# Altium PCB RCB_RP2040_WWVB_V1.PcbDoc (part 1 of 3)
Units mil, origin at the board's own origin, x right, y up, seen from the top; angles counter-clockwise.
Board outline 1250.1 x 2647.64 mil, 10 copper layers (L01-TOP, L02-GND, L03-SIG, L04-GND, L05-PWR, L06-PWR, L07-GND, L08-SIG, L09-GND, L10-BOT), stack 62.1 mil thick; 224 components, 123 nets, 635 pads, 542 vias.
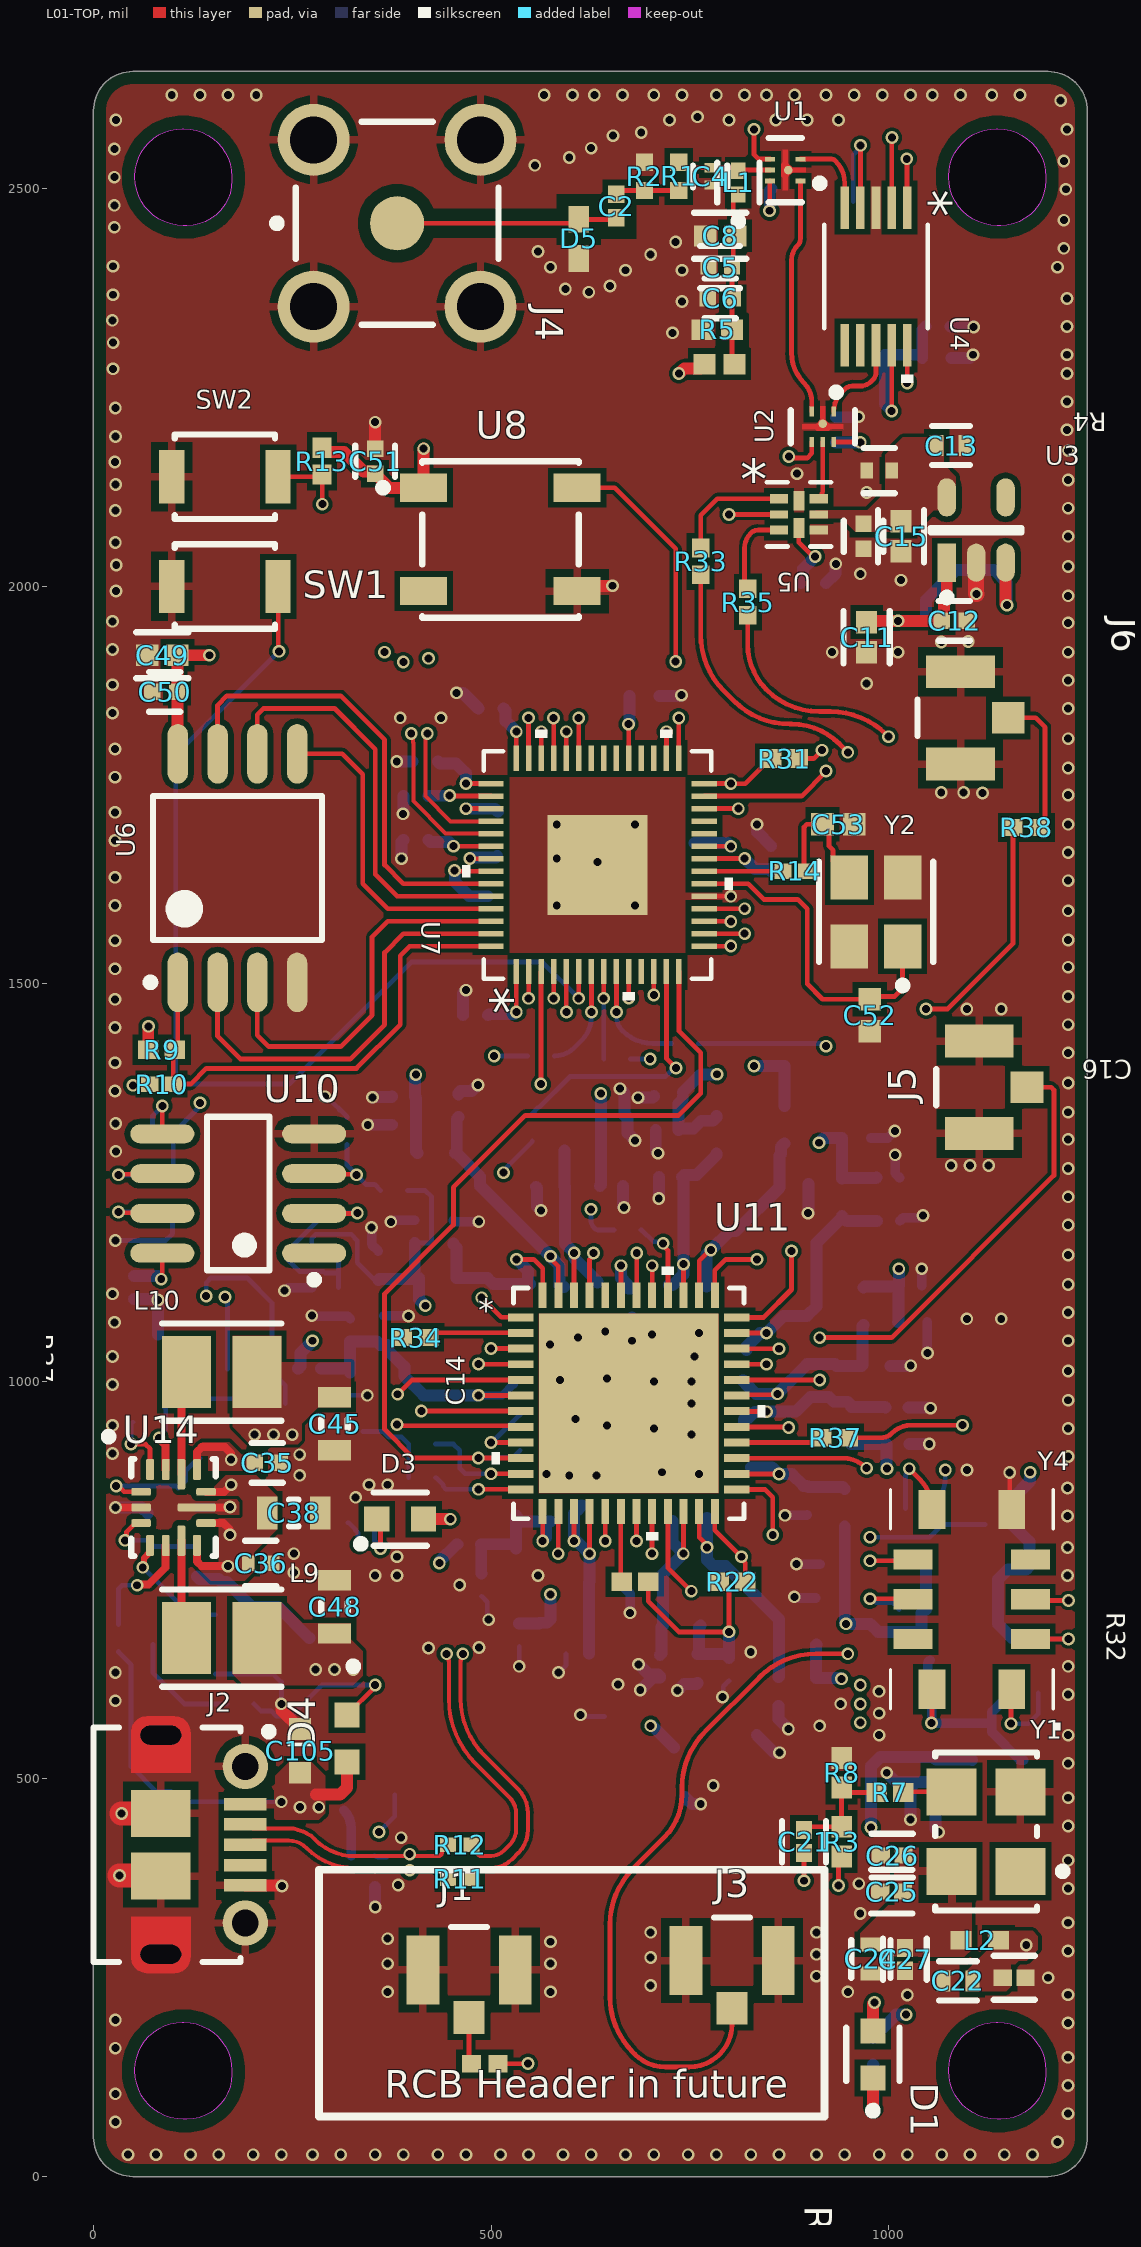
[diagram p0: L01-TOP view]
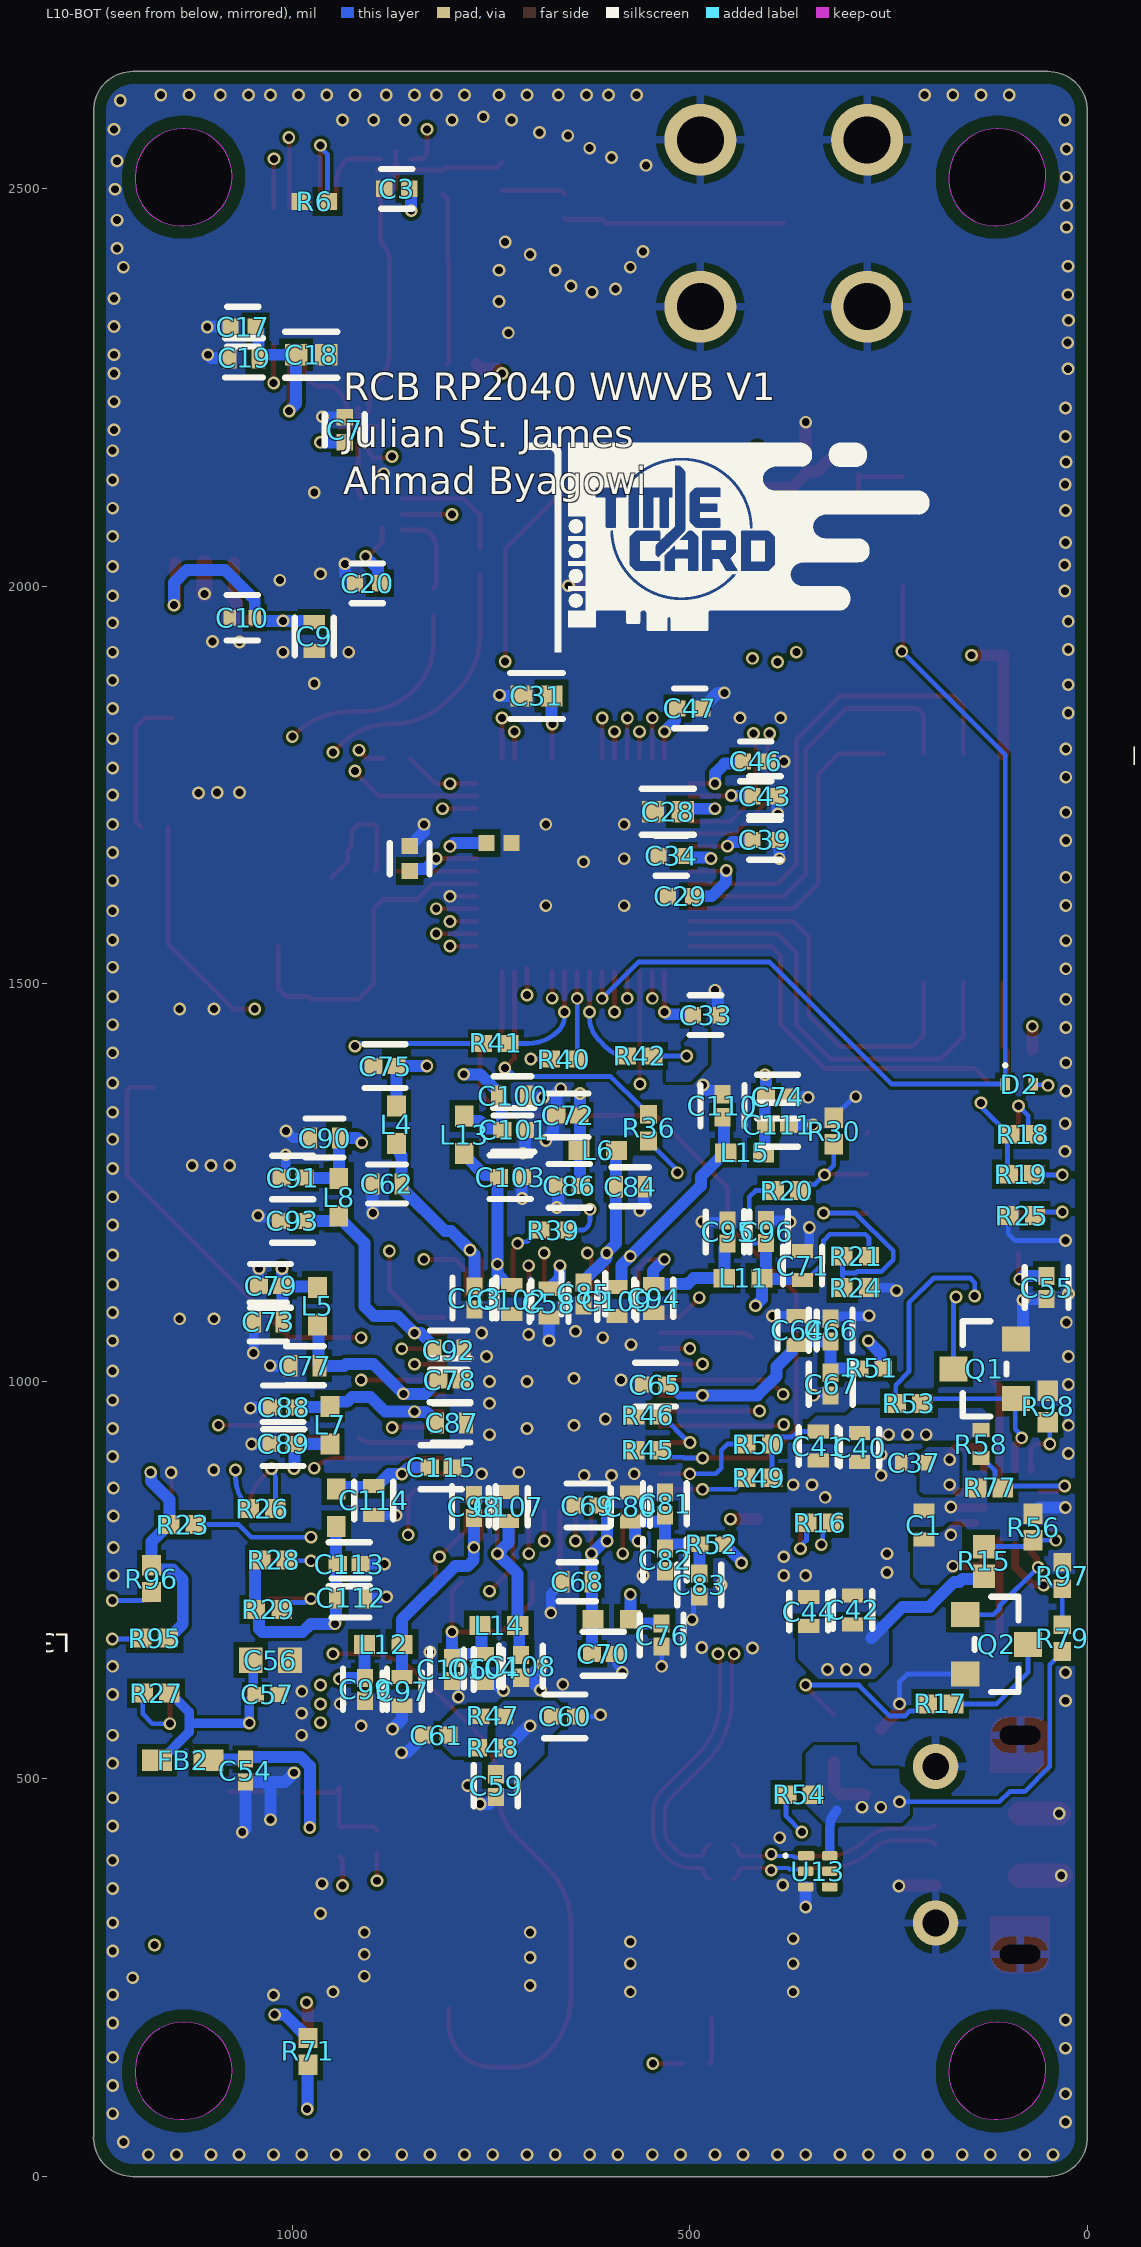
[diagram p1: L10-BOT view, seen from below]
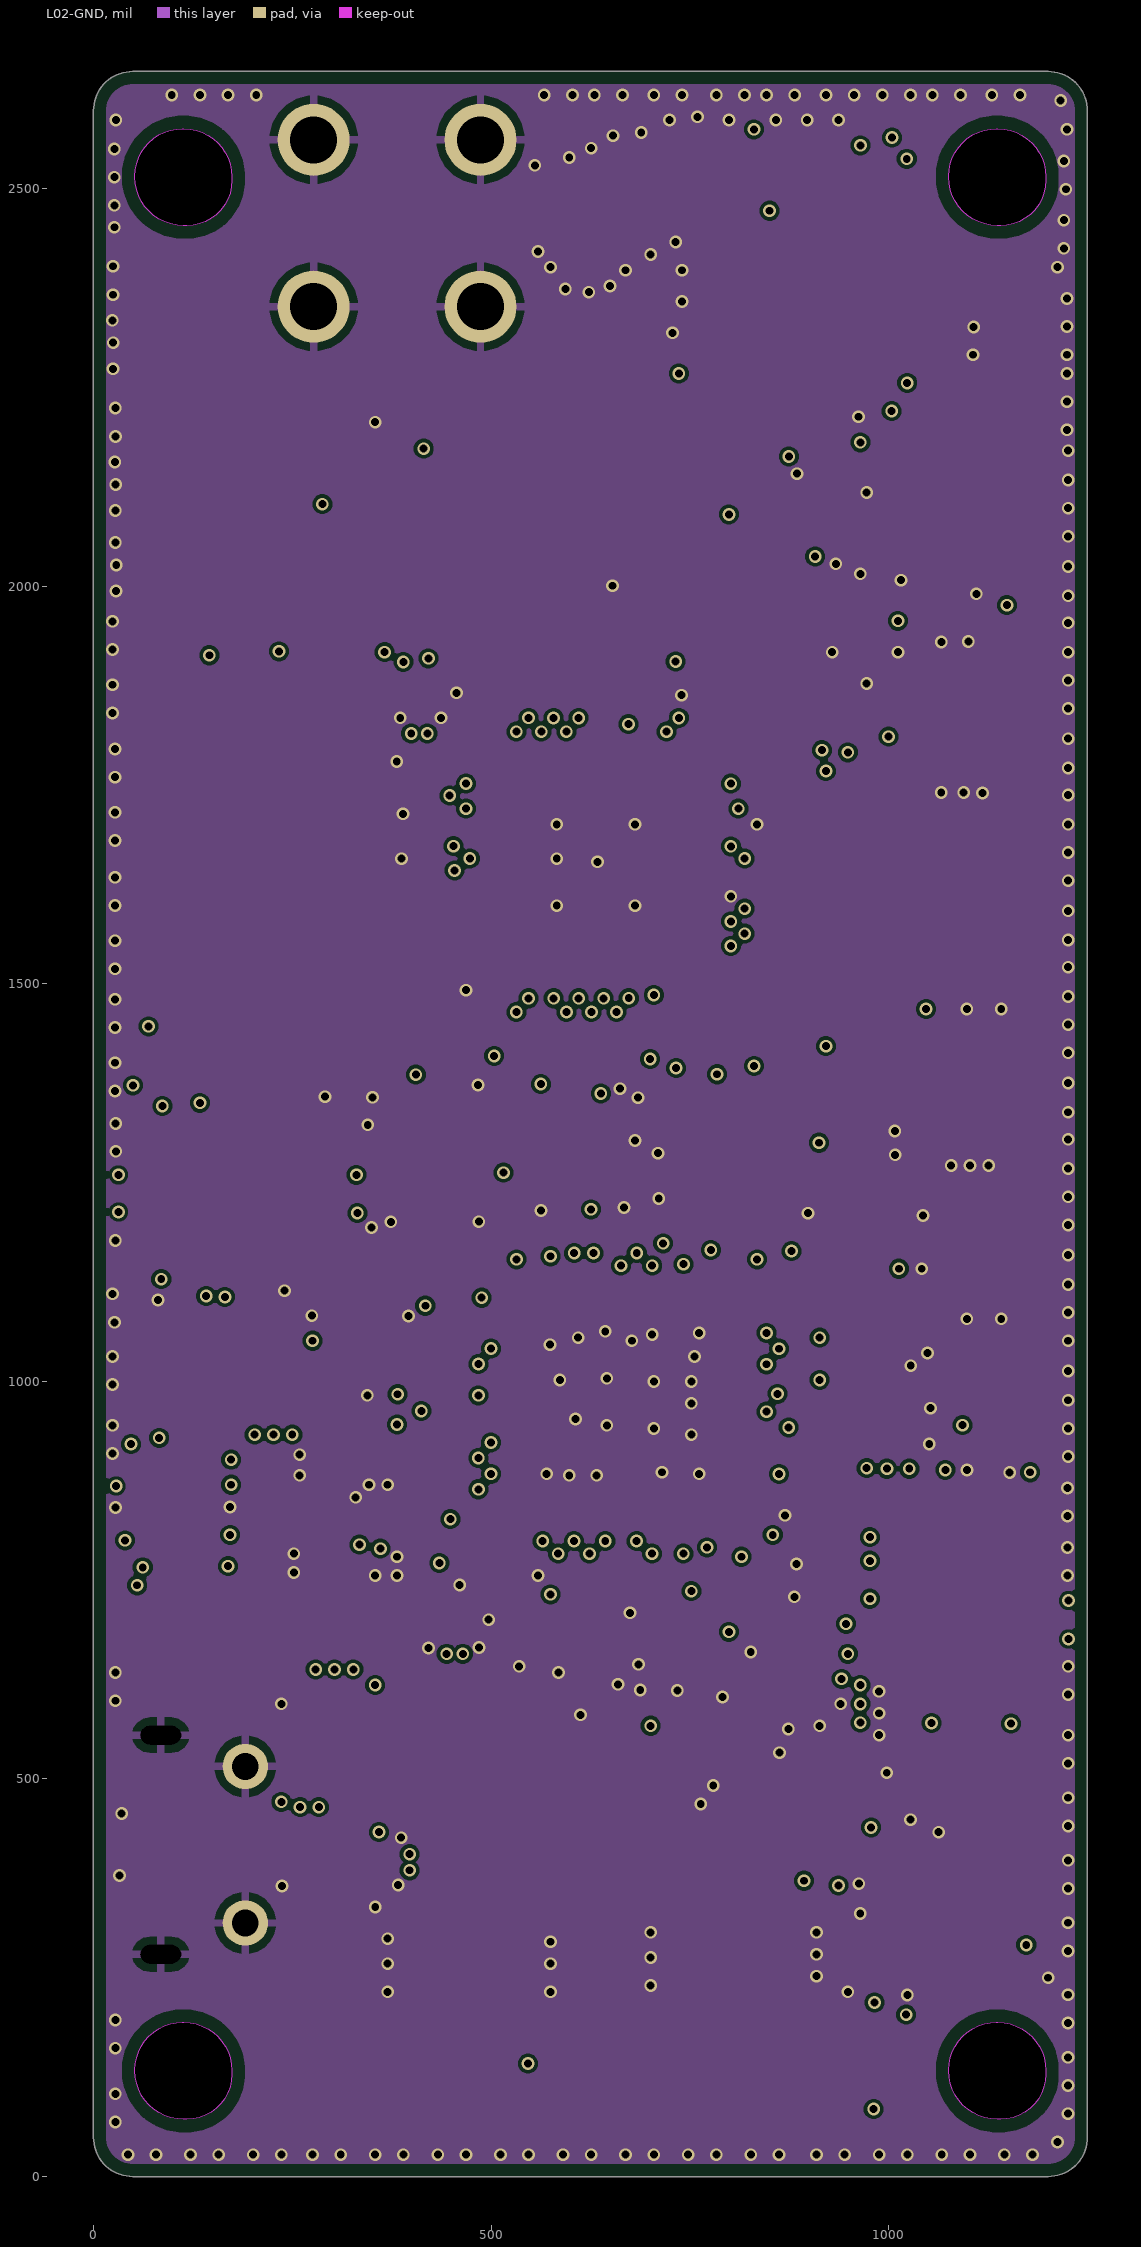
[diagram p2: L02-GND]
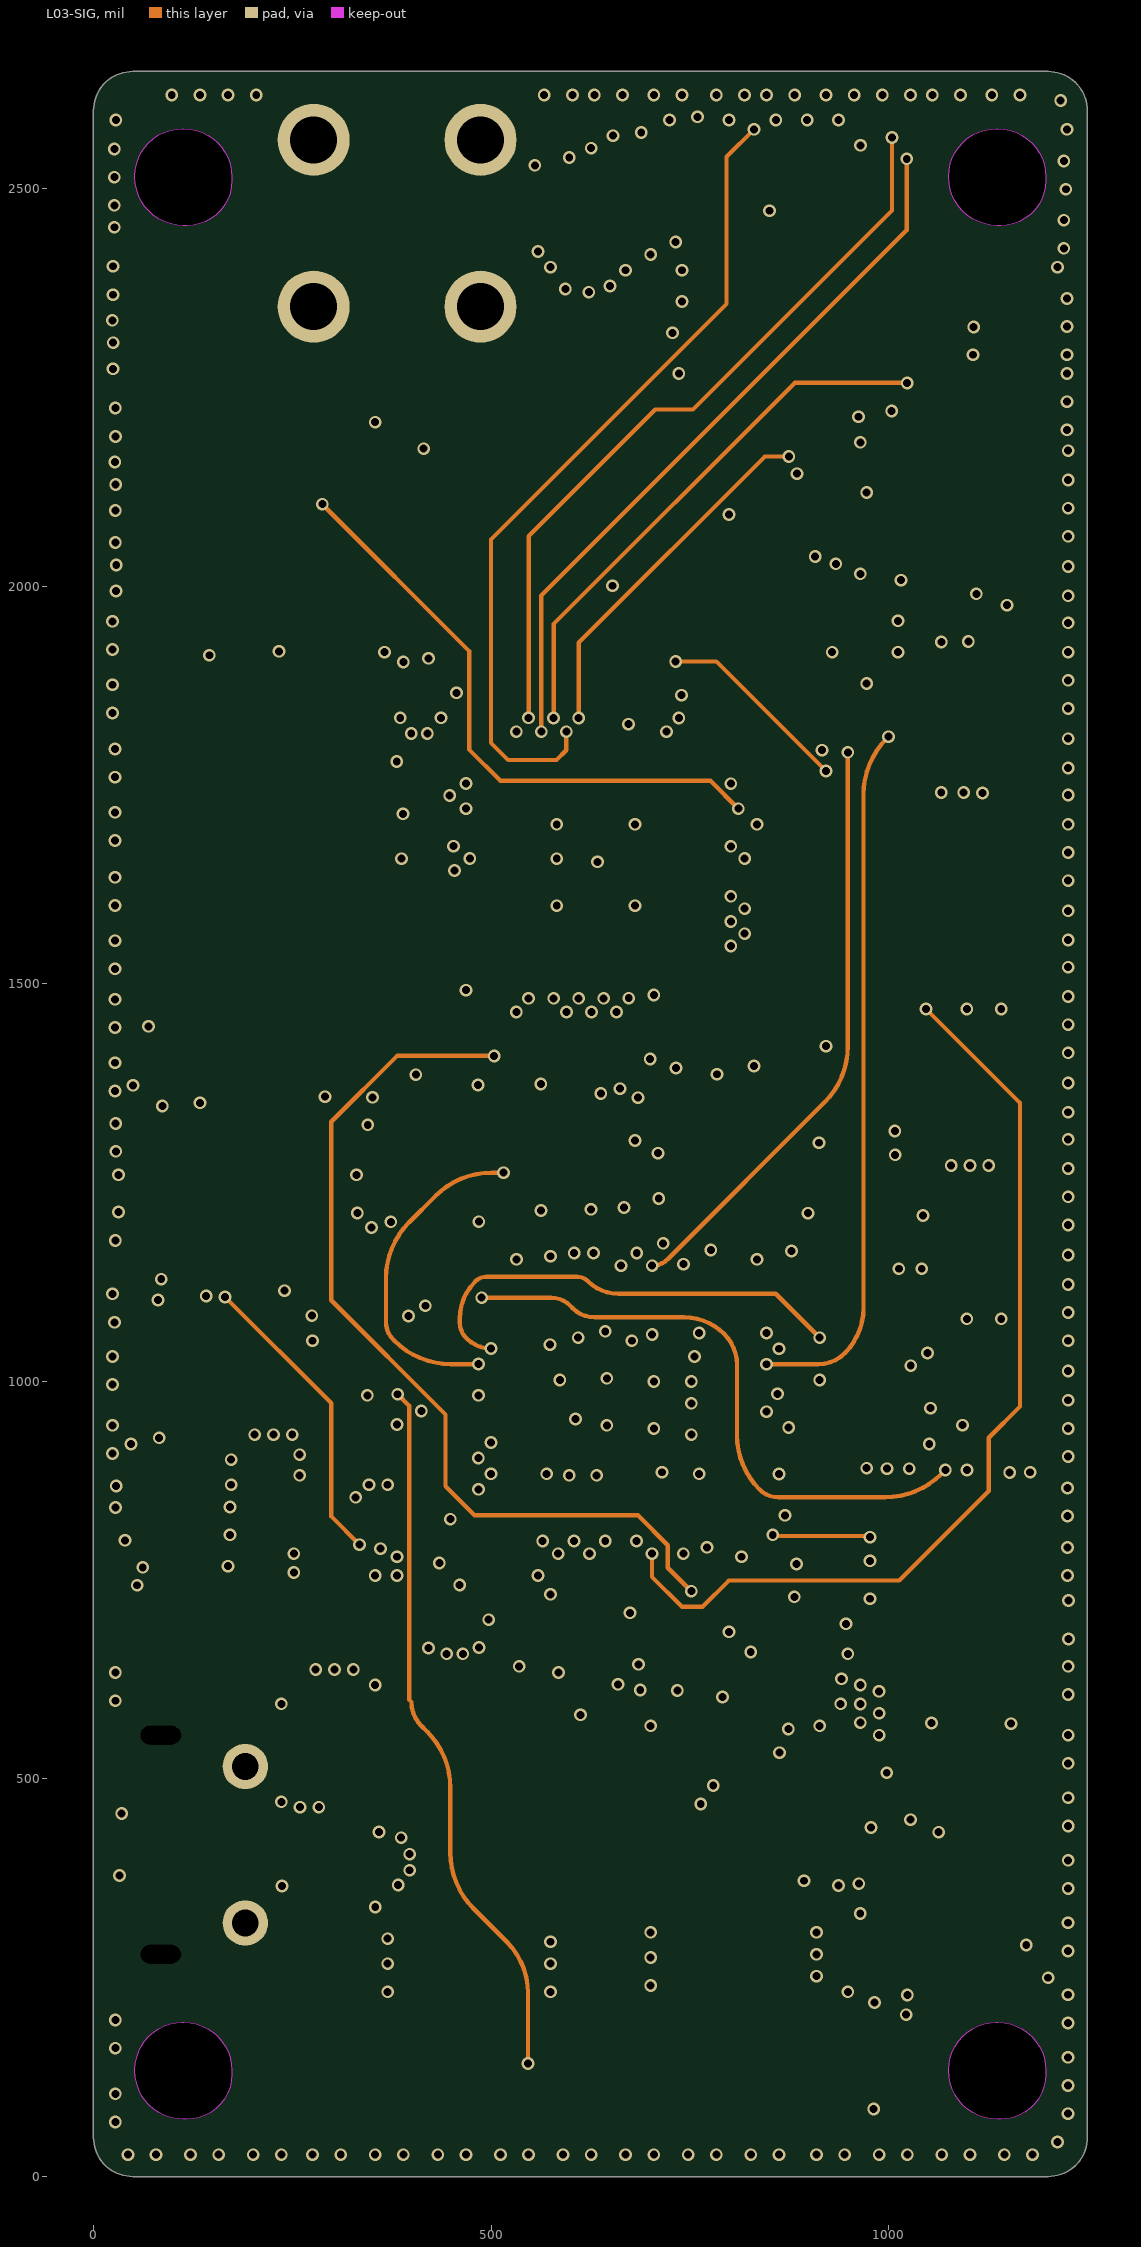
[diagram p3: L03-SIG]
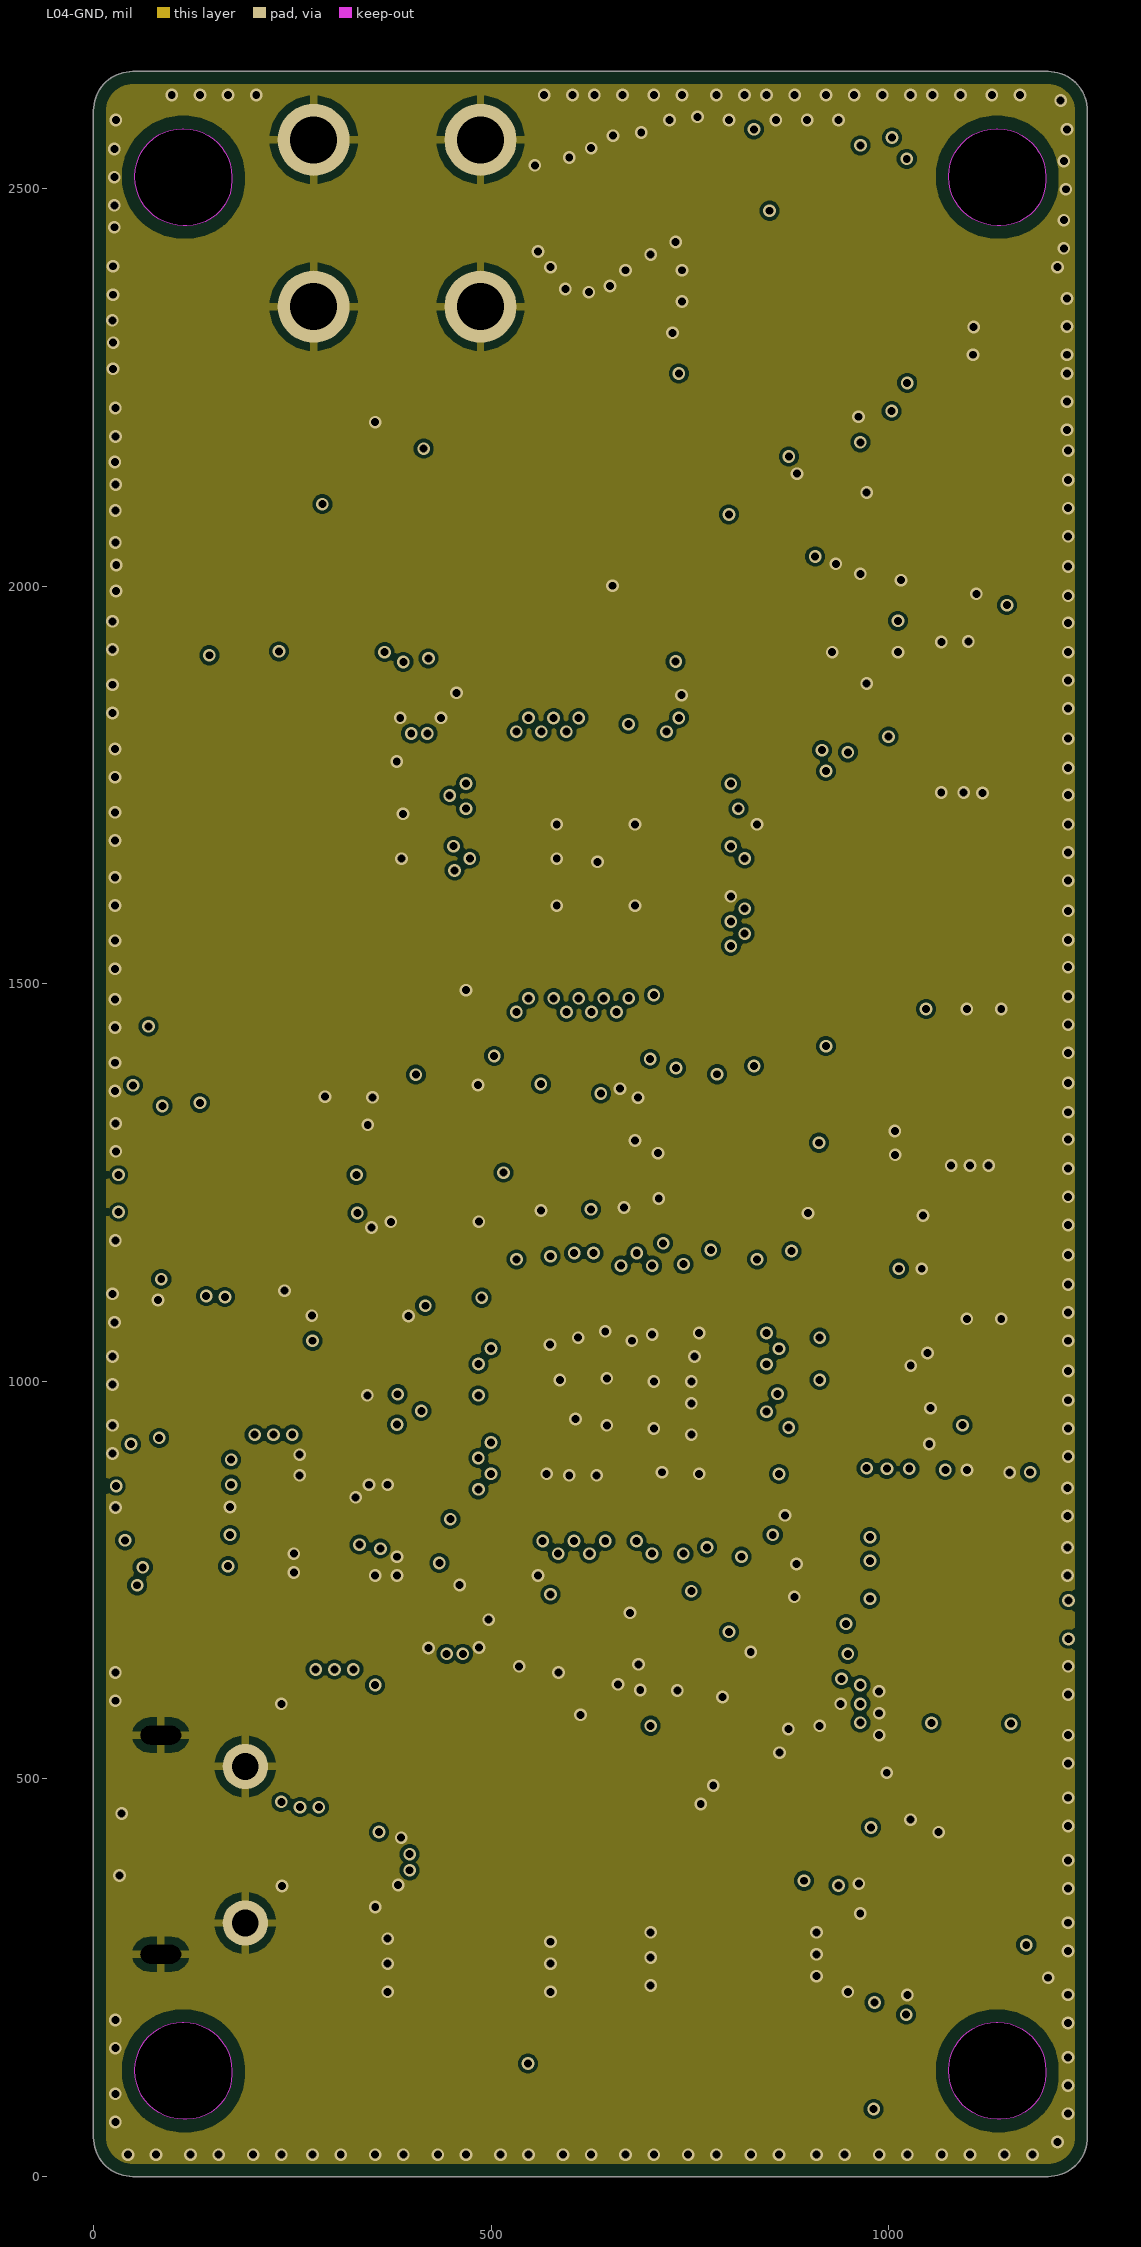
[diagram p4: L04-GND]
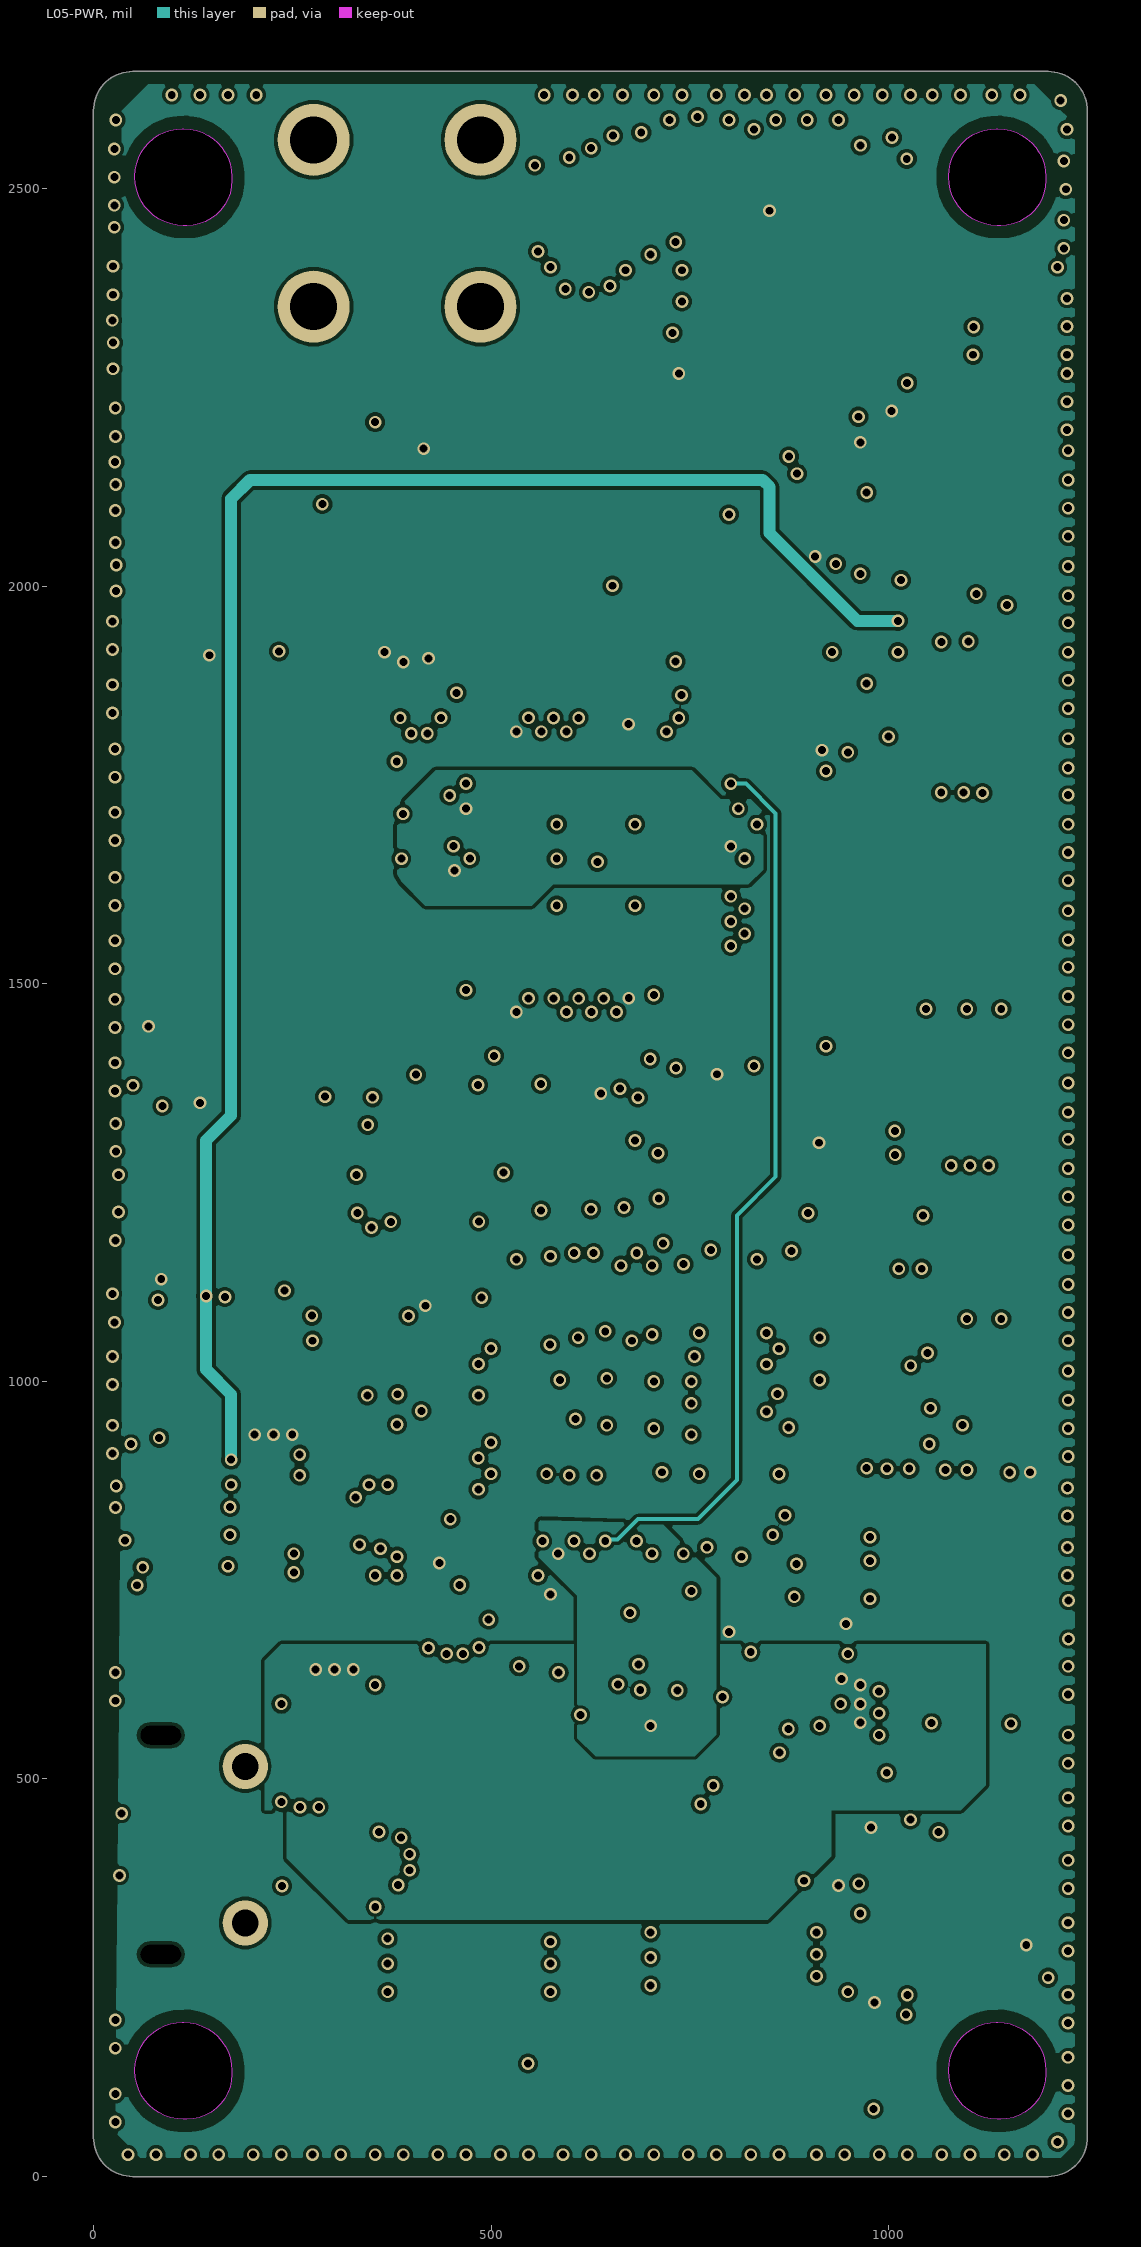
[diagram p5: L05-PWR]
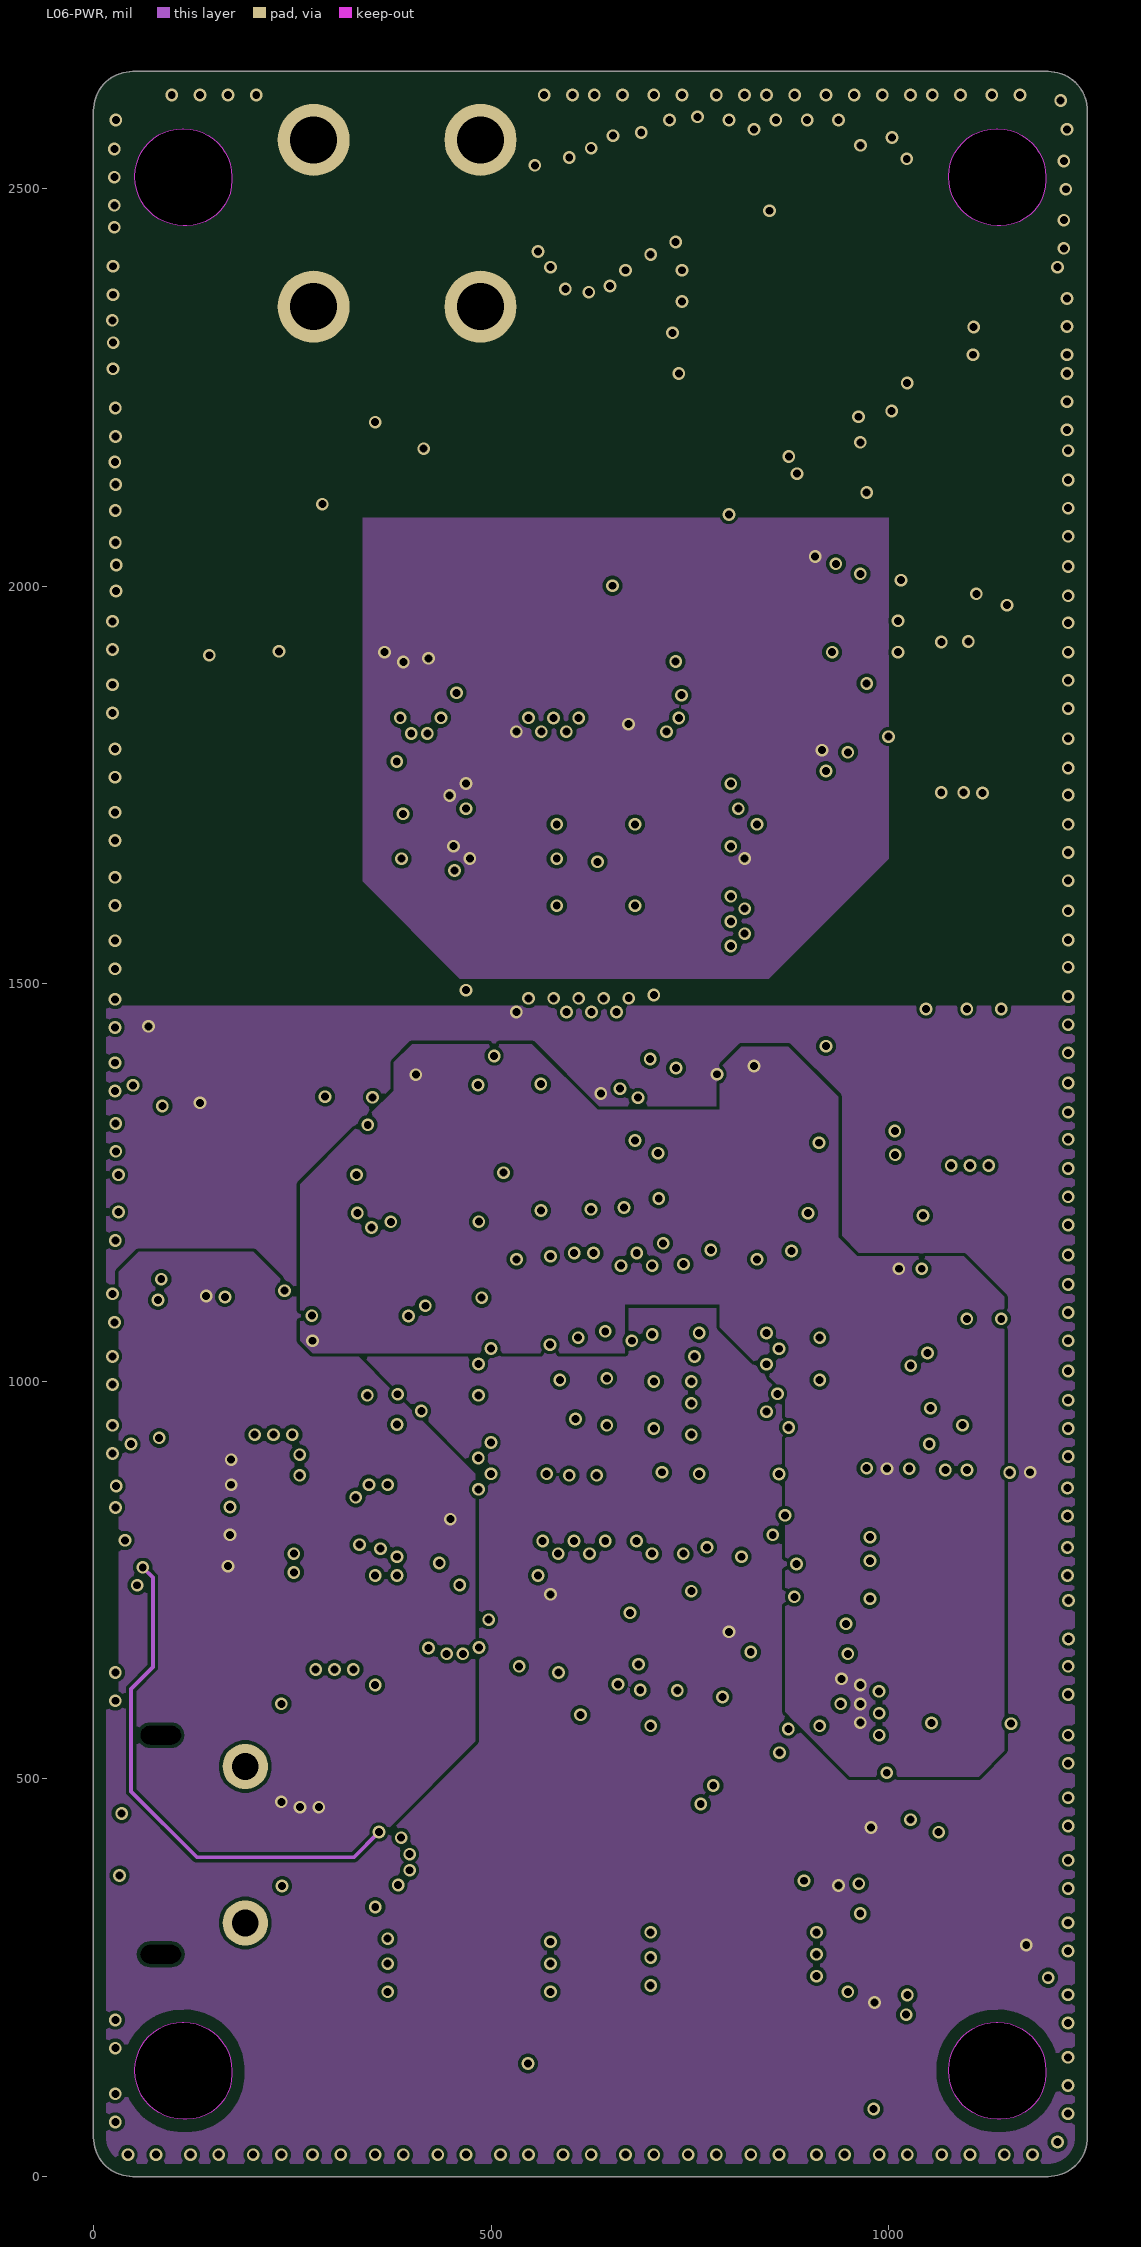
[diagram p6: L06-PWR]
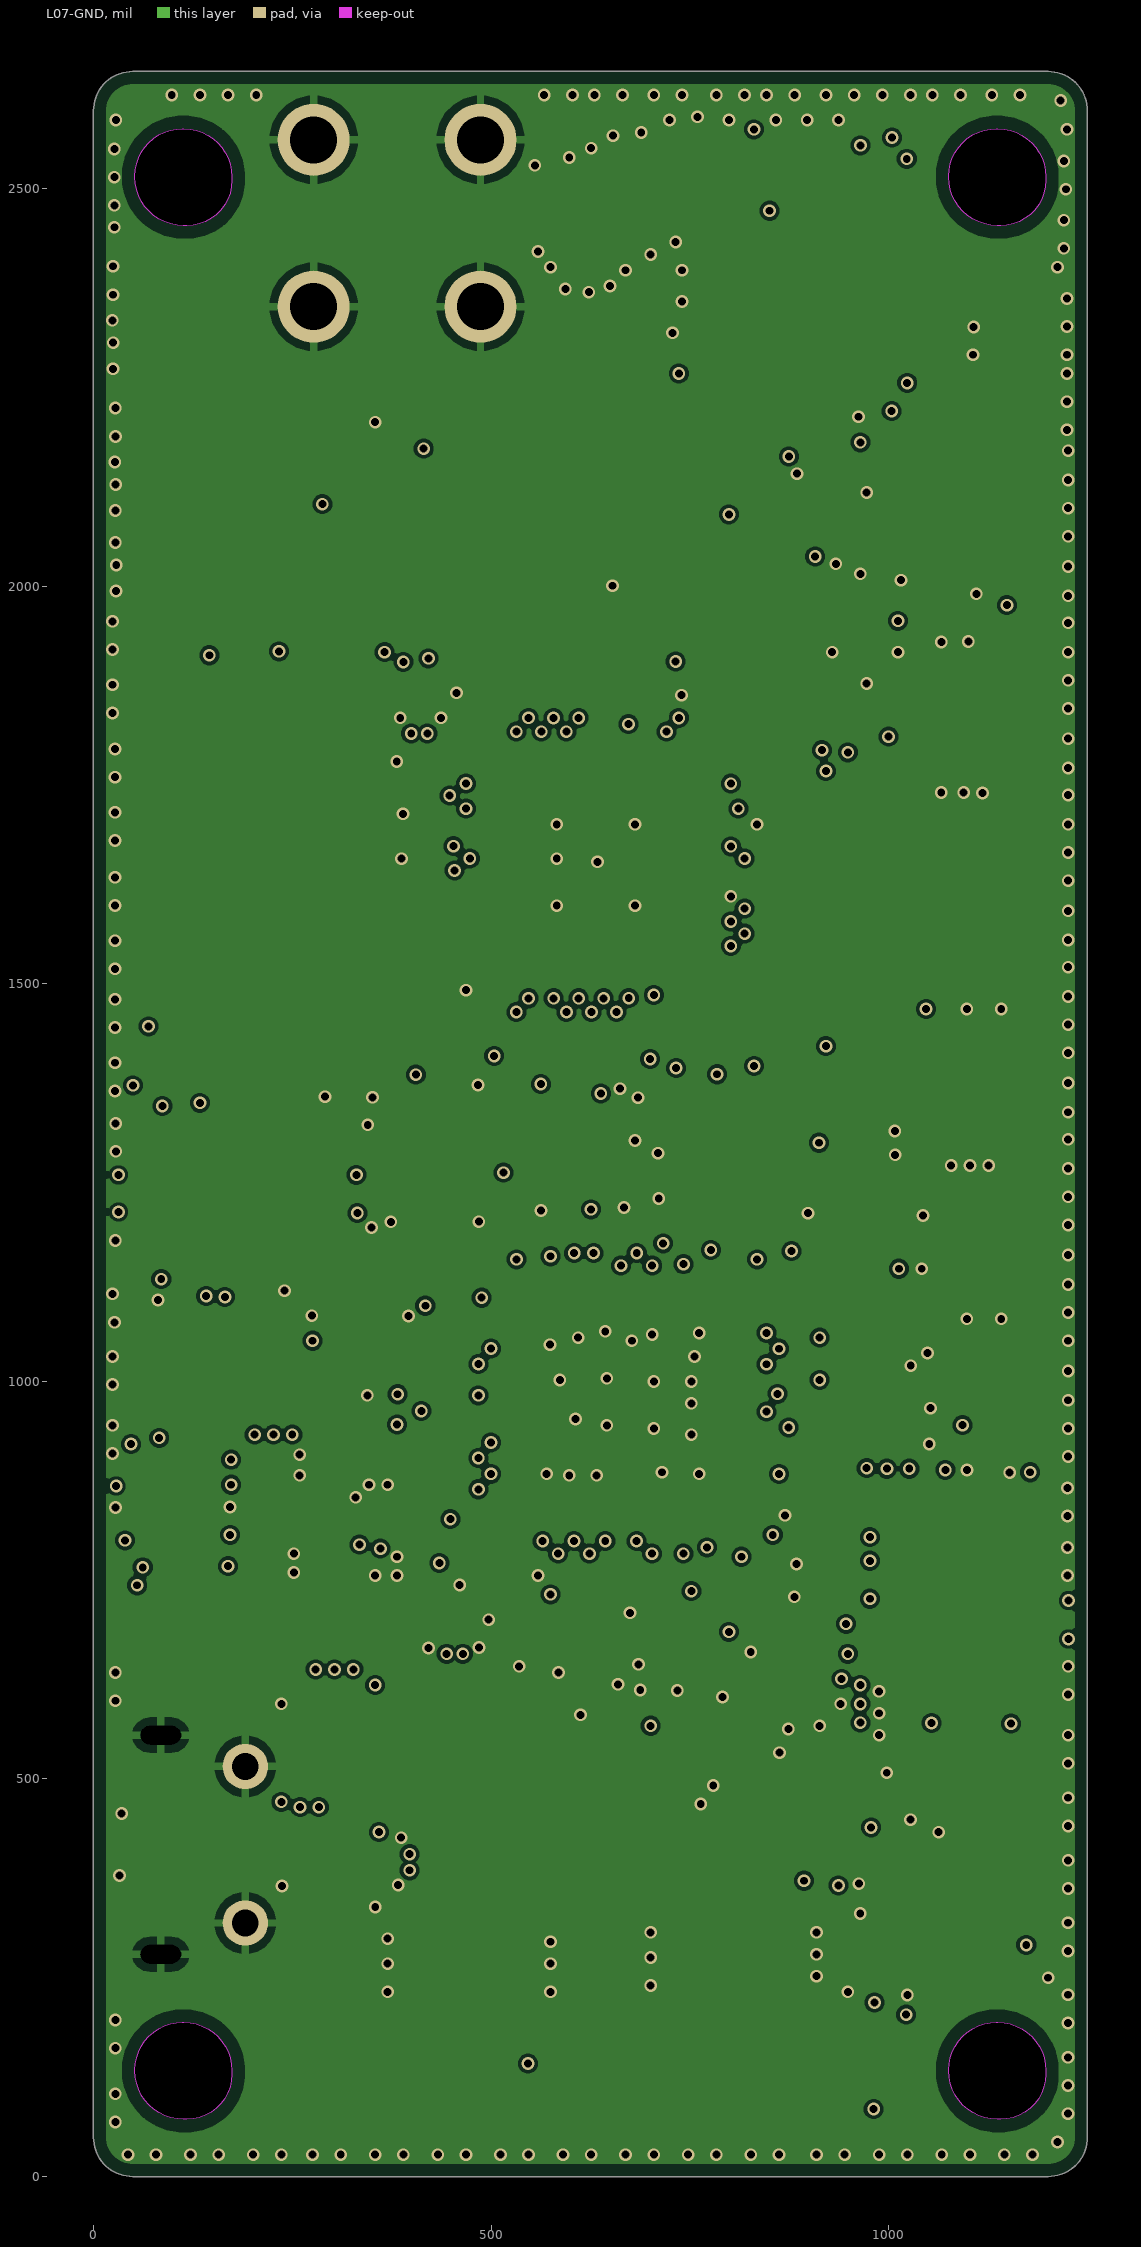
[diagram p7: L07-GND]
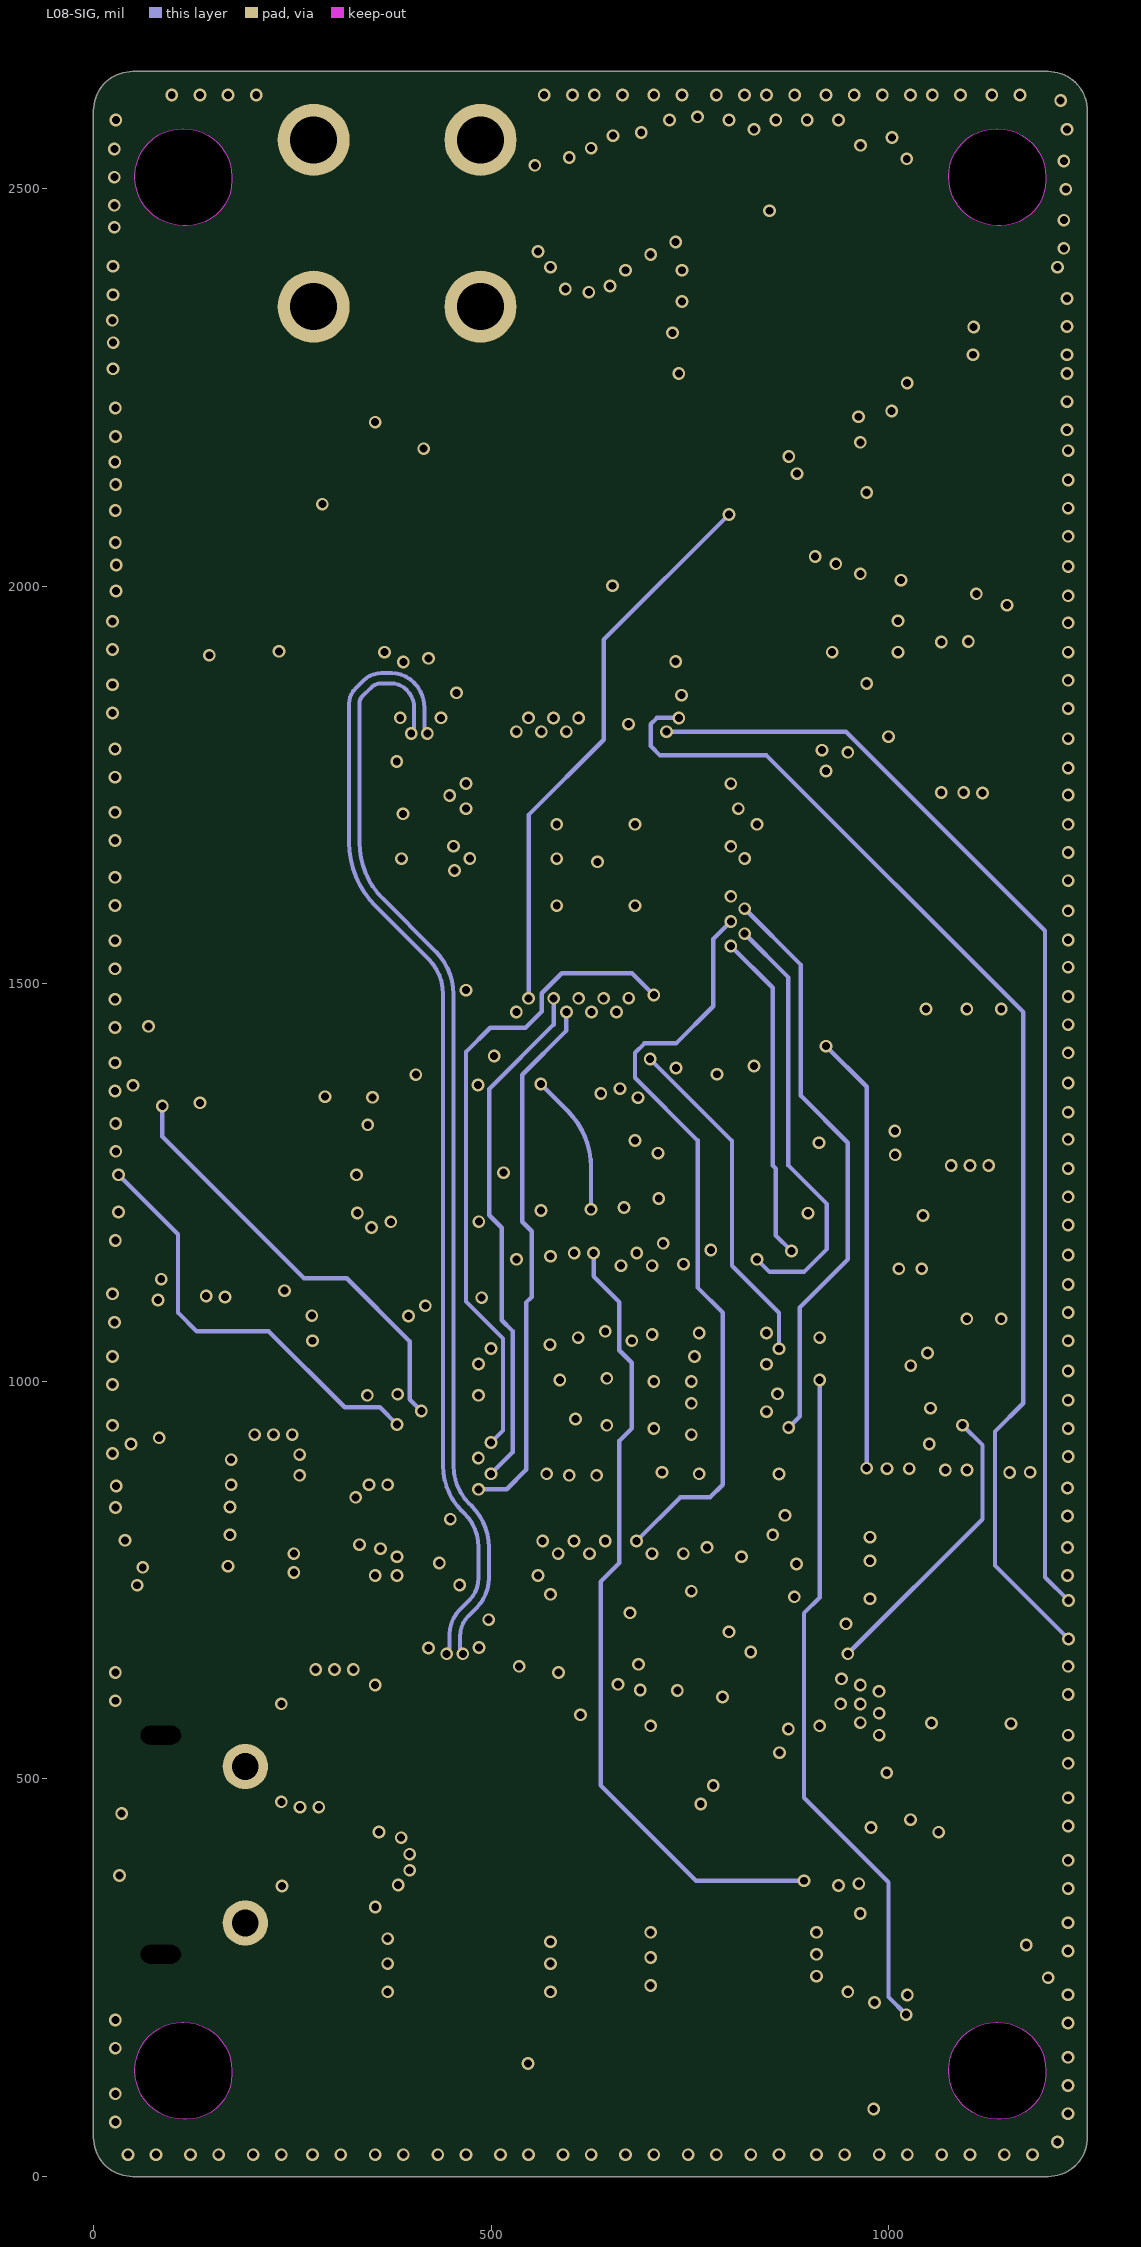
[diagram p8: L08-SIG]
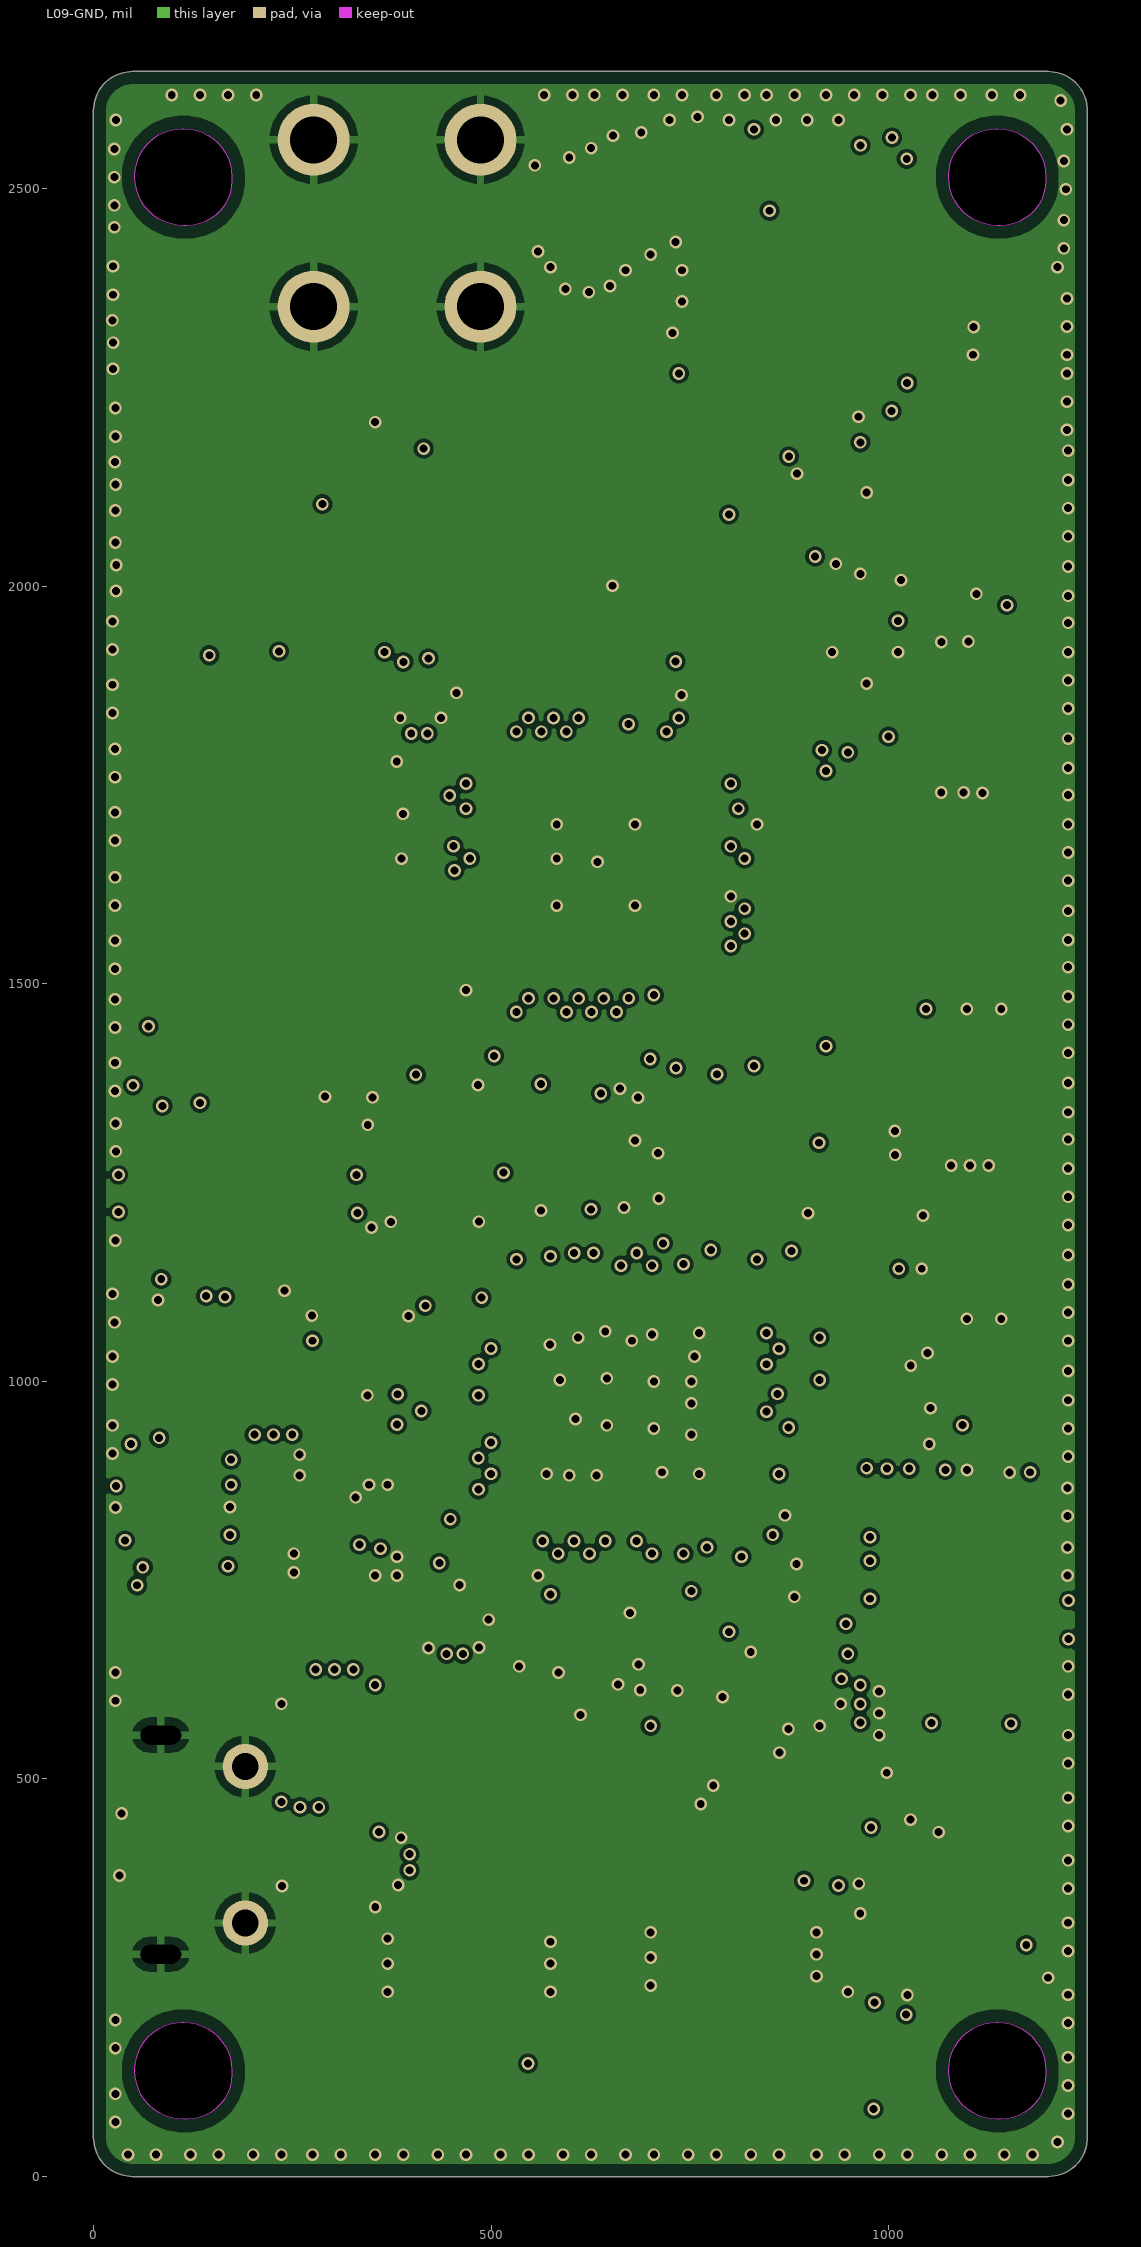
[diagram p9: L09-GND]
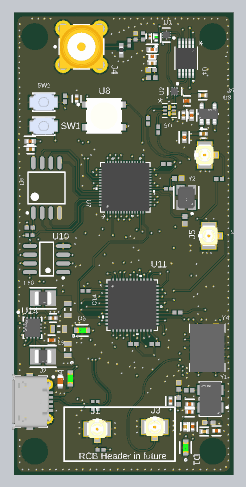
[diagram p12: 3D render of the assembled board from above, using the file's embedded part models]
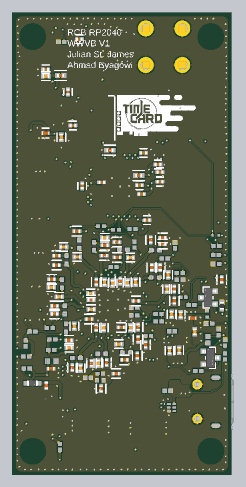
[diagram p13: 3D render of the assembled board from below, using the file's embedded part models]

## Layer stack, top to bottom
L01-TOP: signal copper 1.8
Dielectric 1: prepreg 3.9, 2116, Dk 4.29
L02-GND: signal copper 0.6
Dielectric 4: core 6, PP-006, Dk 4.29
L03-SIG: signal copper 0.6
Dielectric 6: prepreg 7.3, PP-006, Dk 4.29
L04-GND: signal copper 0.6
Dielectric 8: core 6, PP-006, Dk 4.29
L05-PWR: signal copper 0.6
Dielectric 5: prepreg 7.3, PP-006, Dk 4.29
L06-PWR: signal copper 0.6
Dielectric 9: core 6, PP-006, Dk 4.29
L07-GND: signal copper 0.6
Dielectric 7: prepreg 7.3, PP-006, Dk 4.29
L08-SIG: signal copper 0.6
Dielectric 2: core 6, PP-006, Dk 4.29
L09-GND: signal copper 0.6
Dielectric 3: prepreg 3.9, 2116, Dk 4.29
L10-BOT: signal copper 1.8

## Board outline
49.31,0 cw(c49.31,49.31) 0,49.31 0,2598.33 cw(c49.31,2598.33) 49.31,2647.64 1200.79,2647.64 1200.69,2647.64 cw(c1200.69,2598.33) 1250,2598.33 1250,49.31 1250.1,49.31 cw(c1200.79,49.31) 1200.79,0
cut-out: 1137.37,193.9 cw(c1137.37,133.57) 1197.69,133.57 1197.69,128.69 cw(c1140.85,128.69) 1140.85,71.85 1136.75,71.85 cw(c1136.75,132.81) 1075.79,132.81 1075.79,134.11 cw(c1135.57,134.11) 1135.57,193.89
cut-out: 113.75,2575.79 cw(c113.75,2515.46) 174.07,2515.46 174.07,2510.58 cw(c117.23,2510.58) 117.23,2453.74 113.13,2453.74 cw(c113.13,2514.7) 52.17,2514.7 52.17,2516 cw(c111.95,2516) 111.95,2575.78
cut-out: 1137.37,2575.79 cw(c1137.37,2515.46) 1197.69,2515.46 1197.69,2510.58 cw(c1140.85,2510.58) 1140.85,2453.74 1136.75,2453.74 cw(c1136.75,2514.7) 1075.79,2514.7 1075.79,2516 cw(c1135.57,2516) 1135.57,2575.78
cut-out: 113.75,193.9 cw(c113.75,133.57) 174.07,133.57 174.07,128.69 cw(c117.23,128.69) 117.23,71.85 113.13,71.85 cw(c113.13,132.81) 52.17,132.81 52.17,134.11 cw(c111.95,134.11) 111.95,193.89

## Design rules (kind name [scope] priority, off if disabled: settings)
AcuteAngle [All] p1: minimum=6.00000000000000E+0001 checktracksonly=FALSE
BoardOutlineClearance [All] p1: gap=15.75 ignorepadtopadclearanceinfootprint=FALSE
Clearance Clearance_RF [InNetClass('RF')] p1: gap=15 ignorepadtopadclearanceinfootprint=FALSE except(4.3: SMDPad-SMDPad SMDPad-THPad SMDPad-Via SMDPad-Text SMDPad-Hole THPad-THPad THPad-Via THPad-Text THPad-Hole Via-Via Via-Fill Via-Poly Via-Region Via-Text Via-Hole Text-Text Text-Hole)
Clearance [All] p2: gap=4.3 ignorepadtopadclearanceinfootprint=FALSE except(7: SMDPad-Fill SMDPad-Poly SMDPad-Region)
ComponentClearance [All] p1: gap=15.75 collisioncheckmode=3 verticalgap=19.68 showdistances=FALSE
DiffPairsRouting 100_Ohm_Default [InDifferentialPairClass('All Differential Pairs')] p1: maxlimit=10 minlimit=4.43 mostfreqgap=6.68 toplayer_mingap=10 toplayer_prefgap=10 toplayer_minwidth=5 toplayer_maxwidth=5 toplayer_prefwidth=5 midlayer3_mingap=8 midlayer3_maxgap=8 midlayer3_prefgap=8 midlayer3_minwidth=5 midlayer3_maxwidth=5 midlayer3_prefwidth=5 midlayer4_mingap=8 midlayer4_maxgap=8 midlayer4_prefgap=8 midlayer4_minwidth=5 midlayer4_maxwidth=5 midlayer4_prefwidth=5 bottomlayer_mingap=10 bottomlayer_prefgap=10 bottomlayer_minwidth=5 bottomlayer_maxwidth=5 bottomlayer_prefwidth=5 impedanceprofiledriven=TRUE impedanceprofileid={6D9B781E-2234-44CB-9805-C73247B854E7} impedanceprofilevalue=100.000000 maxuncoupledlength=200
HoleSize [All] p1: absolutevalues=TRUE maxlimit=118.11 minlimit=5.91 maxpercent=80.000 minpercent=20.000
HoleToHoleClearance [All] p1: gap=11.81 allowstackedmicrovias=TRUE
MatchedLengths [InDifferentialPairClass('All Differential Pairs')] p1: tolerance=10 checknetsindiffpair=TRUE checkdiffpairvsdiffpair=FALSE checkxsignals=FALSE checkothers=FALSE
MinimumSolderMaskSliver [All] p1: minsoldermaskwidth=3.94 // 0.076mm for Green Soldermask, 0.1 for other color soldermask
PlaneClearance [All] p1: clearance=10
PolygonConnect TH_PolyConnect [HasFootprint('FP-SMA-J-P-H-ST-MT1-MFG') OR HasFootprint('FP-HTSW-104-07-G-D-MFG') OR HasFootprint('USB-MICRO-B_V') OR HasFootprint('FP-U_FL-R-SMT-1_10-MFG') OR HasFootprint('ADA-RGB-1655_V') OR HasFootprint('FP-B3U-1000P-MFG') OR HasFootprint('MCHP-SOIC-SN8_N') OR HasFootprint('FP-SiT5001-3-MFG')] p1: connectstyle=Relief reliefconductorwidth=10 reliefentries=4 polygonreliefangle="90 Angle" airgapwidth=10
PolygonConnect [All] p2: connectstyle=Direct reliefconductorwidth=20 reliefentries=4 polygonreliefangle="90 Angle" airgapwidth=10
RoutingCorners [All] p1: cornerstyle=45-Degree minsetback=98.43 maxsetback=98.43
RoutingVias [All] p1: holewidth=10 width=16 viastyle="Through Hole" minholewidth=10 minwidth=16 maxholewidth=11.81 maxwidth=23.62
SilkToSilkClearance [All] p1: silktosilkclearance=3.94
SilkToSolderMaskClearance [IsPad] p1: minsilkscreentomaskgap=5 clearancetoexposedcopper=TRUE
SolderMaskExpansion [All] p1: expansion=1.97 istentingtop=FALSE
SupplyNets "Schematic Supply Nets_24" [InNet('TX_VFBSD')] p1: voltage=0.000
SupplyNets "Schematic Supply Nets_23" [InNet('RX_VFBSD')] p2: voltage=0.000
SupplyNets "Schematic Supply Nets_22" [InNet('RX_VDD')] p3: voltage=0.000
SupplyNets "Schematic Supply Nets_21" [InNet('TX_VDD')] p4: voltage=0.000
SupplyNets "Schematic Supply Nets_20" [InNet('DPLL_VDD_GPIO')] p5: voltage=0.000
SupplyNets "Schematic Supply Nets_19" [InNet('DPLL_VDDA_FB')] p6: voltage=0.000
SupplyNets "Schematic Supply Nets_18" [InNet('DPLL_VDDO_Q9')] p7: voltage=0.000
SupplyNets "Schematic Supply Nets_17" [InNet('DPLL_VDDA_BG_LC')] p8: voltage=0.000
SupplyNets "Schematic Supply Nets_16" [InNet('DPLL_VDDA_PDCP_XTAL')] p9: voltage=0.000
SupplyNets "Schematic Supply Nets_15" [InNet('P1V8')] p10: voltage=0.000
SupplyNets "Schematic Supply Nets_14" [InNet('DPLL_VDD_DCO_Q11')] p11: voltage=0.000
SupplyNets "Schematic Supply Nets_13" [InNet('P3V3')] p12: voltage=0.000
SupplyNets "Schematic Supply Nets_12" [InNet('GND')] p13: voltage=0.000
SupplyNets "Schematic Supply Nets_11" [InNet('DPLL_VDD_DCO_Q9')] p14: voltage=0.000
SupplyNets "Schematic Supply Nets_10" [InNet('DPLL_VDD_DCO_Q10')] p15: voltage=0.000
SupplyNets "Schematic Supply Nets_9" [InNet('DPLL_VDDO_Q10')] p16: voltage=0.000
SupplyNets "Schematic Supply Nets_8" [InNet('DPLL_VDD_DIG')] p17: voltage=0.000
SupplyNets "Schematic Supply Nets_7" [InNet('VIN')] p18: voltage=0.000
SupplyNets "Schematic Supply Nets_6" [InNet('DPLL_VDD_DCO_Q8')] p19: voltage=0.000
SupplyNets "Schematic Supply Nets_5" [InNet('DPLL_VDDO_Q8')] p20: voltage=0.000
SupplyNets "Schematic Supply Nets_4" [InNet('DPLL_VDD_CLK')] p21: voltage=0.000
SupplyNets "Schematic Supply Nets_3" [InNet('DPLL_VDDO_Q11')] p22: voltage=0.000
SupplyNets "Schematic Supply Nets_2" [InNet('RP_CORE')] p23: voltage=0.000
SupplyNets "Schematic Supply Nets_1" [InNet('ADC_AVDD')] p24: voltage=0.000
SupplyNets "Schematic Supply Nets" [InNet('VBUS_USB')] p25: voltage=0.000
UnRoutedNet [All] p1: checkbadconnections=TRUE
Width [All] p1: maxlimit=100 minlimit=4 preferedwidth=5 toplayer_maxwidth=40 toplayer_prefwidth=6 midlayer3_maxwidth=40 midlayer3_prefwidth=5.5 midlayer4_maxwidth=40 midlayer4_prefwidth=5.5 bottomlayer_maxwidth=40 bottomlayer_prefwidth=6 impedanceprofiledriven=TRUE impedanceprofileid={F524FB06-5728-4647-A49A-4CD393059D1D} impedanceprofilevalue=50.000000 minimp=50.000000 maximp=50.000000 favimp=50.000000
20 further rules are at their usual default settings.

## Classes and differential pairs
component class 07-STM32WL3-TX: U7 U8
component class 06-STM32WL3-RX: D2 SW1 SW2 U5 U6
component class 11-Ice40_FPGA: C7 C74 C104 C106 C107 D4 R15 R16 R17
component class 06-Si5341_PLL: L16 Y1
component class 08-Power: C1 C35 C36 C37 C38 C40 C41 C42 C44 C45 C48 D3 D4 L9 L10 Q1 Q2 R15 R16 R17 R53 R54 R56 R58 R77 R79 R97 R98 U14
component class 07-USB-Prog: C105 J2 U13
component class 04-8A34004_DPLL-2: C62 C63 C64 C65 C66 C67 C68 C69 C70 C71 C72 C73 C74 C75 C76 C77 C78 C79 C80 C81 C82 C83 C84 C85 C86 C87 C88 C89 C90 C91 C92 C93 C94 C95 C96 C97 C98 C99 C100 C101 C102 C103 C104 C106 C107 C108 C109 C110 C111 C112 C113 C114 C115 L3 L4 L5 L6 L7 L8 L11 L12 L13 L14 L15 L16 R51 R52
component class 03-8A34004_DPLL-1: C55 C58 C59 C60 C61 D1 J1 J3 J5 J6 R18 R19 R20 R21 R22 R23 R24 R25 R30 R31 R32 R33 R34 R35 R36 R37 R38 R39 R40 R41 R42 R44 R45 R46 R47 R48 R49 R50 R71 U10 U11
component class 05-TCXO_Crystal: C21 C22 C23 C24 C25 C26 C27 C54 C56 C57 FB2 L2 R3 R7 R8 R26 R27 R28 R29 R95 R96 Y1 Y4
component class 05-SX1276: C31 C32 C33 C34 C39 C43 C46 C47 C49 C58 C59 C60 C101 C102 C103 C108 C109 C110 C111 C112 C113 C114 C115 L7 L8 L11 L12 L13 L14 L15 R23 R32 R33 R46 R47 R48 R49 R50 R51 R52
component class 04-SX1257: C9 C11 C12 C13 C14 C15 C16 C17 C18 C19 C20 C21 C22 C23 C24 C25 C26 C27 C28 C29 L1 L2 L3 R7 R14 U4 U5
component class 02-WWVB_Path: C2 C3 C4 C5 C6 C7 C8 C9 C10 C11 C12 C13 C14 C15 C16 C17 C18 C19 C20 L1 R1 R2 R4 R5 R6 U1 U2 U3 U4 U5
component class 06-RP2040: C28 C29 C30 C31 C32 C33 C34 C39 C43 C46 C47 C49 C50 C51 C52 C53 D2 R9 R10 R11 R12 R13 R14 SW1 SW2 U6 U7 U8 Y2
component class 01-Antennas: D5 J4
net class RF: WWVB_RF_IN
differential pair USB_R: +USB_R_P -USB_R_N
differential pair USB0_D: +USB0_D_P -USB0_D_N

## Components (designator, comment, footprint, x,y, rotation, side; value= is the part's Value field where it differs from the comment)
C1 "10uF_10V_0402" FP-CL05A106MP5NUNC-MFG 205.71,819.4 r90 bottom value=10uF
C2 "5.6nF_25V_0201" CAPC0603X33X15ML03T05 657.48,2478.35 r90 top
C3 "0.1uF_16V_0402" FP-C0402-BB-MFG 868.57,2500 r180 bottom value="0.10 μF"
C4 "1nF_16V_0201" FP-0201-L_0_6_0_09-W_0_3-MFG 775.59,2515.75 r270 top
C5 "10nF_50V_0402" FP-CL165-IPC_C 788.25,2401.57 r180 top
C6 "0.1uF_16V_0402" FP-C0402-BB-MFG 788.25,2362.2 r0 top value="0.10 μF"
C7 "0.1uF_16V_0402" FP-C0402-BB-MFG 934.06,2196.98 r270 bottom value="0.10 μF"
C8 "1uF_16V_0402" FP-0402-L_1_0_0_05-W_0_5-IPC_A 788.25,2440.94 r180 top
C9 "10uF_10V_0402" FP-CL05A106MP5NUNC-MFG 972.44,1937.01 r270 bottom value=10uF
C10 "4.7uF_10V_0402" FP-C1005-050-0_15-MFG 1062.99,1960.63 r0 bottom
C11 "1uF_16V_0402" FP-0402-L_1_0_0_05-W_0_5-IPC_A 972.44,1936.16 r270 top
C12 "0.1uF_16V_0402" FP-C0402-BB-MFG 1082.68,1956.69 r0 top value="0.10 μF"
C13 "10uF_10V_0402" FP-CL05A106MP5NUNC-MFG 1078.74,2177.17 r0 top value=10uF
C14 "4.7uF_10V_0402" FP-C1005-050-0_15-MFG 988.19,2145.67 r180 top
C15 "1uF_16V_0402" FP-0402-L_1_0_0_05-W_0_5-IPC_A 1015.75,2062.99 r270 top
C16 "0.1uF_16V_0402" FP-C0402-BB-MFG 968.5,2062.99 r270 top value="0.10 μF"
C17 "0.1uF_16V_0402" FP-C0402-BB-MFG 1062.11,2326.77 r0 bottom value="0.10 μF"
C18 "1uF_16V_0402" FP-0402-L_1_0_0_05-W_0_5-IPC_A 976.38,2291.34 r180 bottom
C19 "10uF_10V_0402" FP-CL05A106MP5NUNC-MFG 1060.63,2287.4 r0 bottom value=10uF
C20 "0.1uF_16V_0402" FP-C0402-BB-MFG 905.51,2003.94 r0 bottom value="0.10 μF"
C21 "0.1uF_25V_0402" FP-0402-L_1_0_1-W_0_5_0_1-IPC_C 893.7,421.26 r270 top
C22 "10uF_10V_0402" FP-CL05A106MP5NUNC-MFG 1087.17,246.06 r180 top value=10uF
C23 "0.1uF_25V_0402" FP-0402-L_1_0_1-W_0_5_0_1-IPC_C 1158.03,250 r0 top
C24 "10uF_10V_0402" FP-CL05A106MP5NUNC-MFG 977.72,273.76 r270 top value=10uF
C25 "0.1uF_25V_0402" FP-0402-L_1_0_1-W_0_5_0_1-IPC_C 1003.94,358.27 r180 top
C26 "0.1uF_25V_0402" FP-0402-L_1_0_1-W_0_5_0_1-IPC_C 1004.49,403.54 r180 top
C27 "0.1uF_25V_0402" FP-0402-L_1_0_1-W_0_5_0_1-IPC_C 1020.57,273.16 r270 top
C28 "1uF_16V_0402" FP-0402-L_1_0_0_05-W_0_5-IPC_A 527.56,1716.54 r0 bottom
C29 "0.1uF_16V_0402" FP-C0402-BB-MFG 511.81,1610.24 r0 bottom value="0.10 μF"
C30 "0.1uF_16V_0402" FP-C0402-BB-MFG 740.16,1677.17 r180 bottom value="0.10 μF"
C31 "1uF_16V_0402" FP-0402-L_1_0_0_05-W_0_5-IPC_A 692.91,1862.2 r0 bottom
C32 "0.1uF_16V_0402" FP-C0402-BB-MFG 852.36,1657.67 r90 bottom value="0.10 μF"
C33 "0.1uF_16V_0402" FP-C0402-BB-MFG 480.31,1460.63 r180 bottom value="0.10 μF"
C34 "0.1uF_16V_0402" FP-C0402-BB-MFG 523.62,1660.98 r0 bottom value="0.10 μF"
C35 "0.1uF_16V_0402" FP-C0402-BB-MFG 218.5,897.64 r0 top value="0.10 μF"
C36 "4.7uF_10V_0402" FP-C1005-050-0_15-MFG 210.36,771.14 r0 top
C37 "4.7uF_10V_0402" FP-C1005-050-0_15-MFG 218.5,897.64 r0 bottom
C38 "22uF_10V_0603" CAPC1608X100X20ML10 251.97,834.65 r180 top
C39 "0.1uF_16V_0402" FP-C0402-BB-MFG 405.51,1681.1 r180 bottom value="0.10 μF"
C40 "10uF_10V_0402" FP-CL05A106MP5NUNC-MFG 286.42,916.71 r270 bottom value=10uF
C41 "10uF_10V_0402" FP-CL05A106MP5NUNC-MFG 338.58,918.8 r270 bottom value=10uF
C42 "10uF_10V_0402" FP-CL05A106MP5NUNC-MFG 295.28,712.6 r90 bottom value=10uF
C43 "0.1uF_16V_0402" FP-C0402-BB-MFG 405.51,1736.22 r180 bottom value="0.10 μF"
C44 "10uF_10V_0402" FP-CL05A106MP5NUNC-MFG 350.39,710.63 r90 bottom value=10uF
C45 "22uF_10V_0603" CAPC1608X100X20ML10 303.15,946.85 r90 top
C46 "0.1uF_16V_0402" FP-C0402-BB-MFG 417.32,1779.87 r180 bottom value="0.10 μF"
C47 "0.1uF_16V_0402" FP-C0402-BB-MFG 500,1846.46 r180 bottom value="0.10 μF"
C48 "22uF_10V_0603" CAPC1608X100X20ML10 303.15,716.54 r270 top
C49 "1uF_16V_0402" FP-0402-L_1_0_0_05-W_0_5-IPC_A 86.61,1913.39 r180 top
C50 "0.1uF_16V_0402" FP-C0402-BB-MFG 89.56,1867.43 r180 top value="0.10 μF"
C51 "0.1uF_16V_0402" FP-C0402-BB-MFG 354.33,2157.48 r90 top value="0.10 μF"
C52 "22pF_0402" CAPC1005X55X25ML05T05 976.38,1460.63 r90 top
C53 "22pF_0402" CAPC1005X55X25ML05T05 937.01,1700.79 r180 top
C54 "0.1uF_50V_0402" FP-C1005-050-0_05-IPC_C 1059.05,510.5 r90 bottom
C55 "0.1uF_25V_0402" FP-0402-L_1_0_1-W_0_5_0_1-IPC_C 51.18,1118.11 r270 bottom
C56 "10uF_25V_0603" FP-CL10-IPC_C 1027.68,649.61 r180 bottom
C57 "0.1uF_50V_0402" FP-C1005-050-0_05-IPC_C 1031.5,606.3 r0 bottom
C58 "10uF_10V_0402" FP-CL05A106MP5NUNC-MFG 677.17,1098.43 r270 bottom value=10uF
C59 "DNI_0.1uF_25V_0402" FP-0402-L_1_0_1-W_0_5_0_1-IPC_C 744.09,491.68 r270 bottom
C60 "DNI_0.1uF_25V_0402" FP-0402-L_1_0_1-W_0_5_0_1-IPC_C 657.48,578.74 r180 bottom
C61 "2.2nF_25V_0402" CAPC1005X56X25LL10T15 818.9,555.12 r180 bottom
C62 "10uF_10V_0402" FP-CL05A106MP5NUNC-MFG 881.07,1248.42 r0 bottom value=10uF
C63 "0.1uF_25V_0402" FP-0402-L_1_0_1-W_0_5_0_1-IPC_C 771.1,1104.89 r270 bottom
C64 "10uF_10V_0402" FP-CL05A106MP5NUNC-MFG 365.1,1064.24 r90 bottom value=10uF
C65 "0.1uF_25V_0402" FP-0402-L_1_0_1-W_0_5_0_1-IPC_C 543.31,996.06 r0 bottom
C66 "0.1uF_25V_0402" FP-0402-L_1_0_1-W_0_5_0_1-IPC_C 322.92,1064.53 r90 bottom
C67 "0.1uF_25V_0402" FP-0402-L_1_0_1-W_0_5_0_1-IPC_C 322.83,996.62 r270 bottom
C68 "10uF_10V_0402" FP-CL05A106MP5NUNC-MFG 641.73,748.03 r0 bottom value=10uF
C69 "0.1uF_25V_0402" FP-0402-L_1_0_1-W_0_5_0_1-IPC_C 629.02,843.97 r0 bottom
C70 "0.1uF_25V_0402" FP-0402-L_1_0_1-W_0_5_0_1-IPC_C 608.76,657.48 r180 bottom
C71 "10uF_10V_0402" FP-CL05A106MP5NUNC-MFG 358.27,1145.67 r90 bottom value=10uF
C72 "0.1uF_25V_0402" FP-0402-L_1_0_1-W_0_5_0_1-IPC_C 653.54,1334.65 r0 bottom
C73 "10uF_10V_0402" FP-CL05A106MP5NUNC-MFG 1030.34,1074.8 r0 bottom value=10uF
C74 "0.1uF_25V_0402" FP-0402-L_1_0_1-W_0_5_0_1-IPC_C 389.76,1358.27 r180 bottom
C75 "0.1uF_25V_0402" FP-0402-L_1_0_1-W_0_5_0_1-IPC_C 883.41,1396.72 r0 bottom
C76 "0.1uF_25V_0402" FP-0402-L_1_0_1-W_0_5_0_1-IPC_C 535.43,681.1 r270 bottom
C77 "10uF_10V_0402" FP-CL05A106MP5NUNC-MFG 984.25,1019.68 r0 bottom value=10uF
C78 "0.1uF_25V_0402" FP-0402-L_1_0_1-W_0_5_0_1-IPC_C 801.72,1001.39 r180 bottom
C79 "0.1uF_25V_0402" FP-0402-L_1_0_1-W_0_5_0_1-IPC_C 1027.38,1120.31 r0 bottom
C80 "10uF_10V_0402" FP-CL05A106MP5NUNC-MFG 574.8,842.2 r90 bottom value=10uF
C81 "0.1uF_25V_0402" FP-0402-L_1_0_1-W_0_5_0_1-IPC_C 531.5,846.07 r90 bottom
C82 "0.1uF_25V_0402" FP-0402-L_1_0_1-W_0_5_0_1-IPC_C 531.5,775.59 r270 bottom
C83 "0.1uF_25V_0402" FP-0402-L_1_0_1-W_0_5_0_1-IPC_C 488.19,744.09 r270 bottom
C84 "10uF_10V_0402" FP-CL05A106MP5NUNC-MFG 574.87,1244.94 r180 bottom value=10uF
C85 "0.1uF_25V_0402" FP-0402-L_1_0_1-W_0_5_0_1-IPC_C 633.86,1110.15 r270 bottom
C86 "0.1uF_25V_0402" FP-0402-L_1_0_1-W_0_5_0_1-IPC_C 651.55,1246 r0 bottom
C87 "10uF_10V_0402" FP-CL05A106MP5NUNC-MFG 799.72,947.91 r180 bottom value=10uF
C88 "0.1uF_25V_0402" FP-0402-L_1_0_1-W_0_5_0_1-IPC_C 1010.79,967.29 r0 bottom
C89 "0.1uF_25V_0402" FP-0402-L_1_0_1-W_0_5_0_1-IPC_C 1011.66,921.35 r0 bottom
C90 "10uF_10V_0402" FP-CL05A106MP5NUNC-MFG 959.51,1306.2 r0 bottom value=10uF
C91 "0.1uF_25V_0402" FP-0402-L_1_0_1-W_0_5_0_1-IPC_C 999.37,1256.41 r0 bottom
C92 "10uF_10V_0402" FP-CL05A106MP5NUNC-MFG 803.15,1039.37 r180 bottom value=10uF
C93 "0.1uF_25V_0402" FP-0402-L_1_0_1-W_0_5_0_1-IPC_C 999.8,1202.03 r0 bottom
C94 "10uF_10V_0402" FP-CL05A106MP5NUNC-MFG 545.41,1104.59 r270 bottom value=10uF
C95 "0.1uF_25V_0402" FP-0402-L_1_0_1-W_0_5_0_1-IPC_C 452.61,1188.06 r90 bottom
C96 "0.1uF_25V_0402" FP-0402-L_1_0_1-W_0_5_0_1-IPC_C 404.08,1188.42 r90 bottom
C97 "10uF_10V_0402" FP-CL05A106MP5NUNC-MFG 861.84,610.33 r270 bottom value=10uF
C98 "0.1uF_25V_0402" FP-0402-L_1_0_1-W_0_5_0_1-IPC_C 771.65,842.52 r90 bottom
C99 "0.1uF_25V_0402" FP-0402-L_1_0_1-W_0_5_0_1-IPC_C 908.58,612.73 r270 bottom
C100 "10uF_10V_0402" FP-CL05A106MP5NUNC-MFG 722.96,1359.19 r180 bottom value=10uF
C101 "0.1uF_25V_0402" FP-0402-L_1_0_1-W_0_5_0_1-IPC_C 721.62,1316.46 r180 bottom
C102 "10uF_10V_0402" FP-CL05A106MP5NUNC-MFG 724.05,1102.91 r270 bottom value=10uF
C103 "0.1uF_25V_0402" FP-0402-L_1_0_1-W_0_5_0_1-IPC_C 725.8,1257.03 r180 bottom
C104 "10uF_10V_0402" FP-CL05A106MP5NUNC-MFG 759.84,638.78 r270 bottom value=10uF
C105 "10uF_16V_0603" FP-0603-L_1_6_0_2-W_0_8_0-MFG 259.84,535.43 r90 top
C106 "0.1uF_25V_0402" FP-0402-L_1_0_1-W_0_5_0_1-IPC_C 799.21,637.8 r270 bottom
C107 "10uF_10V_0402" FP-CL05A106MP5NUNC-MFG 728.35,842.52 r90 bottom value=10uF
C108 "0.1uF_25V_0402" FP-0402-L_1_0_1-W_0_5_0_1-IPC_C 712.6,641.73 r270 bottom
C109 "10uF_10V_0402" FP-CL05A106MP5NUNC-MFG 591.86,1100.8 r270 bottom value=10uF
C110 "0.1uF_25V_0402" FP-0402-L_1_0_1-W_0_5_0_1-IPC_C 458.98,1346.76 r90 bottom
C111 "0.1uF_25V_0402" FP-0402-L_1_0_1-W_0_5_0_1-IPC_C 389.76,1322.83 r180 bottom
C112 "10uF_10V_0402" FP-CL05A106MP5NUNC-MFG 926.72,727.66 r180 bottom value=10uF
C113 "0.1uF_25V_0402" FP-0402-L_1_0_1-W_0_5_0_1-IPC_C 928.52,770.13 r180 bottom
C114 "10uF_10V_0402" FP-CL05A106MP5NUNC-MFG 897.64,850.39 r270 bottom value=10uF
C115 "0.1uF_25V_0402" FP-0402-L_1_0_1-W_0_5_0_1-IPC_C 812.81,892.05 r180 bottom
D1 "LTST-C190GKT" FP-LTST-C190GKT-MFG 980.31,153.54 r90 top
D2 "NSR0340P2T5G" ONSC-SOD-923-2-514AB-01_B_V 85.63,1374.02 r180 bottom
D3 "LTST-C190GKT" FP-LTST-C190GKT-MFG 385.83,826.77 r0 top
D4 "LTST-C190GKT" FP-LTST-C190GKT-MFG 318.9,551.18 r270 top
D5 "PESD0402-140" FP-PESD0402-MFG 610.24,2437.01 r90 top value=0.25pF
FB2 "742792641" FP-742792641-MFG 1137.8,523.62 r180 bottom
J1 "U.FL-R-SMT-1(10)" FP-U_FL-R-SMT-1_10-MFG 472.44,259.84 r180 top
J2 "105017-0001" USB-MICRO-B_V 137.8,417.32 r270 top
J3 "U.FL-R-SMT-1(10)" FP-U_FL-R-SMT-1_10-MFG 803.15,271.65 r180 top
J4 "SMA-J-P-H-ST-MT1" FP-SMA-J-P-H-ST-MT1-MFG 381.89,2456.69 r0 top
J5 "U.FL-R-SMT-1(10)" FP-U_FL-R-SMT-1_10-MFG 1114.17,1370.08 r270 top
J6 "U.FL-R-SMT-1(10)" FP-U_FL-R-SMT-1_10-MFG 1090.55,1834.65 r270 top
L1 "LQG15HH47NJ02D" FP-LQG15HH_02-IPC_C 811.02,2507.87 r90 top
L2 "742792780" SMD-0402 1114.73,297.24 r180 top
L3 "742792780" SMD-0402 598.43,700.79 r0 bottom
L4 "742792780" SMD-0402 869.04,1322.97 r270 bottom
L5 "742792780" SMD-0402 968.5,1094.49 r270 bottom
L6 "742792780" SMD-0402 615.89,1290.64 r180 bottom
L7 "742792780" SMD-0402 952.76,945.05 r90 bottom
L8 "742792780" SMD-0402 941.69,1231.79 r270 bottom
L9 "DFE252012PD-R47M=P2" FP-DFE252012C-IPC_A 161.42,677.17 r0 top
L10 "DFE252012PD-R47M=P2" FP-DFE252012C-IPC_A 161.42,1011.81 r0 top locked
L11 "742792780" SMD-0402 433.07,1129.92 r0 bottom
L12 "742792780" SMD-0402 885.83,669.29 r180 bottom
L13 "742792780" SMD-0402 783.72,1310.12 r270 bottom
L14 "742792780" SMD-0402 740.16,692.91 r180 bottom
L15 "742792780" SMD-0402 431.16,1287.4 r0 bottom
L16 "742792780" SMD-0402 944.88,841.04 r90 bottom
Q1 "2N7002KT1G" FP-318-08-MFG 129.17,1015.75 r0 bottom
Q2 "2N7002KT1G" FP-318-08-MFG 114.17,669.29 r180 bottom
R1 "1K_1%_0402" RESC1005X40X25NL05T05 736.22,2515.75 r270 top
R2 "1K_1%_0402" RESC1005X40X25NL05T05 692.91,2515.75 r270 top
R3 "100_1%_0402" RESC1005X40X25ML05T10 940.94,421.26 r270 top
R4 "100_1%_0402" RESC1005X40X25ML05T10 787.4,2279.53 r180 top
R5 "100_1%_0402" RESC1005X40X25ML05T10 784.45,2322.83 r0 top
R6 "0_5%_0402" RESC1005X40X25NL05T10 972.44,2484.25 r180 bottom
R7 "49.9_1%_0402" RESC1005X40X25NL10T10 1001.7,482.91 r180 top
R8 "100_1%_0402" RESC1005X40X25ML05T10 940.94,507.87 r270 top
R9 "10K_1%_0402" RESC1005X40X25NL10T10 85.63,1417.32 r0 top
R10 "1K_1%_0402" RESC1005X40X25LL10T10 85.63,1374.02 r0 top
R11 "27_1%_0402" RESC1005X40X25LL05T10 460.63,374.02 r180 top
R12 "27_1%_0402" RESC1005X40X25LL05T10 460.63,417.32 r180 top
R13 "10K_1%_0402" RESC1005X40X25NL10T10 287.4,2157.48 r270 top
R14 "1K_1%_0402" RESC1005X40X25LL10T10 881.89,1641.73 r180 top
R15 "20K_1%_0402" RESC1005X40X25ML10T10 130.24,773.57 r90 bottom
R16 "330_1%_0402" RESC1005X40X25NL10T10 336.62,822.18 r0 bottom
R17 "330_1%_0402" RESC1005X40X25NL10T10 185.04,594.49 r0 bottom
R18 "4.7K_1%_0402" RESC1005X40X25NL10T10 81.26,1310.97 r180 bottom
R19 "4.7K_1%_0402" RESC1005X40X25NL10T10 83.59,1260.63 r180 bottom
R20 "4.7K_1%_0402" RESC1005X40X25NL10T10 377.95,1240.16 r0 bottom
R21 "DNI_4.7K_1%_0402" RESC1005X40X25NL10T10 291.34,1157.48 r180 bottom
R22 "4.7K_1%_0402" RESC1005X40X25NL10T10 803.15,748.03 r0 top
R23 "4.7K_1%_0402" RESC1005X40X25NL10T10 1137.99,820.02 r180 bottom
R24 "4.7K_1%_0402" RESC1005X40X25NL10T10 291.34,1118.11 r0 bottom
R25 "4.7K_1%_0402" RESC1005X40X25NL10T10 82.68,1208.66 r180 bottom
R26 "49.9_1%_0402" RESC1005X40X25NL10T10 1037.99,840.16 r180 bottom
R27 "4.7K_1%_0402" RESC1005X40X25NL10T10 1171.46,608.07 r0 bottom
R28 "4.7K_1%_0402" RESC1005X40X25NL10T10 1023.62,775.59 r0 bottom
R29 "4.7K_1%_0402" RESC1005X40X25NL10T10 1030.24,713.19 r0 bottom
R30 "DNI_4.7K_1%_0402" RESC1005X40X25NL10T10 318.9,1314.96 r90 bottom
R31 "4.7K_1%_0402" RESC1005X40X25NL10T10 869.09,1783.46 r0 top
R32 "4.7K_1%_0402" RESC1005X40X25NL10T10 681.1,748.03 r0 top
R33 "0_5%_0402" RESC1005X40X25NL05T10 763.78,2031.5 r90 top
R34 "0_5%_0402" RESC1005X40X25NL05T10 405.51,1055.12 r0 top
R35 "0_5%_0402" RESC1005X40X25NL05T10 822.83,1980.32 r90 top
R36 "0_5%_0402" RESC1005X40X25NL05T10 551.85,1319.28 r270 bottom
R37 "0_5%_0402" RESC1005X40X25NL05T10 933.07,929.13 r0 top
R38 "0_5%_0402" RESC1005X40X25NL05T10 1173.23,1696.85 r0 top
R39 "0_5%_0402" RESC1005X40X25NL05T10 671.8,1190.47 r180 bottom
R40 "0_5%_0402" RESC1005X40X25NL05T10 658.46,1405.51 r180 bottom
R41 "0_5%_0402" RESC1005X40X25NL05T10 744.09,1425.2 r180 bottom
R42 "0_5%_0402" RESC1005X40X25NL05T10 562.99,1409.45 r0 bottom
R44 "0_5%_0402" RESC1005X40X25NL05T10 492.13,141.73 r0 top
R45 "4.7K_1%_0402" RESC1005X40X25NL10T10 553.23,913.39 r0 bottom
R46 "4.7K_1%_0402" RESC1005X40X25NL10T10 553.23,957.6 r0 bottom
R47 "0_5%_0402" RESC1005X40X25LL10T10 748.03,578.74 r180 bottom
R48 "DNI_1K_1%_0402" RESC1005X40X25NL05T05 748.03,539.37 r180 bottom
R49 "4.7K_1%_0402" RESC1005X40X25NL10T10 413.31,878.76 r180 bottom
R50 "4.7K_1%_0402" RESC1005X40X25NL10T10 413.39,921.26 r180 bottom
R51 "0_5%_0402" RESC1005X40X25LL10T10 271.65,1016.31 r0 bottom
R52 "0_5%_0402" RESC1005X40X25LL10T10 472.44,795.28 r0 bottom
R53 "10K_1%_0402" RESC1005X40X25NL10T10 224.41,972.44 r0 bottom
R54 "10K_1%_0402" RESC1005X40X25NL10T10 362.2,480.32 r180 bottom
R56 "10K_1%_0402" RESC1005X40X25NL10T10 68.24,816.93 r270 bottom
R58 "45.3K_1%_0402" RESC0402(1005)_L 133.86,921.26 r270 bottom value="45300.00 Ohm"
R71 "330_1%_0402" RESC1005X40X25NL10T10 980.31,157.48 r270 bottom
R77 "10K_1%_0402" RESC1005X40X25NL10T10 123.03,866.14 r180 bottom
R79 "0_5%_0402" RESC1005X40X25NL05T10 31.5,677.17 r270 bottom
R95 "4.7K_1%_0402" RESC1005X40X25NL10T10 1173.23,677.17 r180 bottom
R96 "4.7K_1%_0402" RESC1005X40X25NL10T10 1177.17,751.97 r90 bottom
R97 "DNI_0_5%_0402" RESC1005X40X25NL05T10 31.5,755.91 r270 bottom
R98 "8.06K_1%_0402" RESC1005X40X25ML05T05 49.69,968.5 r270 bottom
SW1 "B3U-1000P" FP-B3U-1000P-MFG 165.35,2000 r180 top
SW2 "B3U-1000P" FP-B3U-1000P-MFG 165.35,2137.8 r180 top
U1 "SKY13585-679LF" FP-SKY13585-679LF-MFG 870.08,2523.62 r180 top
U2 "SKY13585-679LF" FP-SKY13585-679LF-MFG 917.32,2200.79 r270 top
U3 "RT9080-33GJ5" FP-RT9080-33GJ5-IPC_C 1110.24,2070.87 r90 top
U4 "MAX9939AUB+T" 21-0061L_MXM 984.25,2389.76 r270 top
U5 "ADS7052IRUGR" RUG8_TEX 887.2,2090.55 r0 top
U6 "W25Q128FVSIG" WINB-SOIC-8_M 181.1,1645.67 r90 top
U7 "RP2040" IC57_RP2040 634,1649.61 r90 top
U8 "1655" ADA-RGB-1655_V 511.81,2059.06 r0 top
U10 "24LC1026-I/SN" MCHP-SOIC-SN8_N 182.09,1236.42 r180 top
U11 "8A34004E-000NBG" NBG48P1_REN 673.23,972.44 r0 top locked
U13 "TPD3E001DRYR" DRY0006A 339.17,383.86 r180 bottom
U14 "TPS62442QWRPSRQ1" FP-RQR0014A-MFG 100.71,841.54 r0 top
Y1 "SIT5001AC-3E-33N0-40.000000X" FP-SiT5001-3-MFG 1122.6,433.86 r90 top
Y2 "ABM8G-12.000MHZ-18-D2Y-T" FP-ABM8G-MFG 984.25,1590.55 r90 top
Y4 "SiTime_SiT5501AC-WU-33E0-10T" SITIME_SPL-086-CQFN-010-C07050_REV_DRAFT 1104.72,725.98 r180 top

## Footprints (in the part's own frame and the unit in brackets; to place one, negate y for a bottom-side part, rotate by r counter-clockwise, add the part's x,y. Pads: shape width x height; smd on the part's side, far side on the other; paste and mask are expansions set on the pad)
21-0061L_MXM [mil]
  rect 53.5x11 smd paste+0 mask+0: 1(-86.75,39.37) 2(-86.75,19.69) 3(-86.75,0) 4(-86.75,-19.68) 5(-86.75,-39.37) 6(86.75,-39.37) 7(86.75,-19.68) 8(86.75,0) 9(86.75,19.69) 10(86.75,39.37)
  silkscreen extent -65,-65 134,65, body extent -99,-60 99,60, height 43
ADA-RGB-1655_V [mm] "SMD, 4-Leads, Body 5x5mm"
  rect 1.5x0.9 smd: 1(-2.45,1.65) 2(-2.45,-1.65) 3(2.45,-1.65) 4(2.45,1.65)
  silkscreen extent -3.87,-2.5 2.5,2.5, body extent -2.7,-2.5 2.7,2.5, height 1.68
CAPC0603X33X15ML03T05 [mm] "Chip Capacitor, 2-Leads, Body 0.60x0.30mm, IPC Low Density"
  rect 0.56x0.52 smd: 1(-0.38,0) 2(0.38,0)
  body extent -0.31,-0.17 0.32,0.16, height 0.33
CAPC1005X55X25ML05T05 [mm] "Chip Capacitor, 2-Leads, Body 1.00x0.50mm, IPC Low Density"
  rect 0.72x0.72 smd: 1(-0.51,0) 2(0.51,0)
  body extent -0.53,-0.28 0.53,0.27, height 0.55
CAPC1005X56X25LL10T15 [mm] "Chip Capacitor, 2-Leads, Body 1.00x0.50mm, IPC High Density"
  rect 0.58x0.54 smd: 1(-0.39,0) 2(0.39,0)
  body extent -0.55,-0.3 0.55,0.3, height 0.56
CAPC1608X100X20ML10 [mm] "Chip Capacitor, 2-Leads, Body 1.70x0.90mm, IPC Low Density"
  rect 0.65x1.05 smd: 1(-0.85,0) 2(0.85,0)
  silkscreen extent -0.15,-0.43 0.15,0.43, body extent -0.85,-0.45 0.85,0.45, height 1
DRY0006A [mm] "SON, 6-Leads, Body 1.45x1mm, Pitch 0.5mm"
  rrect33% 0.52x0.3 smd: 1(-0.37,0.5)
  rrect33% 0.49x0.3 smd: 2(-0.385,0) 3(-0.385,-0.5) 4(0.385,-0.5) 5(0.385,0) 6(0.385,0.5)
  silkscreen extent -1.08,0.45 -0.98,0.55, body extent -0.5,-0.72 0.5,0.72, height 0.6
FP-0201-L_0_6_0_09-W_0_3-MFG [mm]
  rect 0.3x0.35 smd paste+0 mask+0: 1(-0.275,0) 2(0.275,0)
  silkscreen extent -0.35,-0.55 0.35,0.55, body extent -0.53,-0.3 0.53,0.3, height 0.25
FP-318-08-MFG [mm]
  rect 0.9x0.8 smd paste+0 mask+0: 1(-1,0.95) 2(-1,-0.95) 3(1,0)
  silkscreen extent -0.7,-1.52 0.7,1.52, body extent -1.2,-1.45 1.2,1.45, height 1.11
FP-0402-L_1_0_0_05-W_0_5-IPC_A [mil]
  rect 28.16x26.48 smd paste+0 mask+0: 1(-18.84,0) 2(18.84,0)
  silkscreen extent -33,-29 33,29, body extent -41,-21 41,21, height 10
FP-0402-L_1_0_1-W_0_5_0_1-IPC_C [mil]
  rect 22.88x20.16 smd paste+0 mask+0: 1(-14.39,0) 2(14.39,0)
  silkscreen extent -26,-28 26,28, body extent -20,-10 20,10, height 22
FP-0603-L_1_6_0_2-W_0_8_0-MFG [mm]
  rect 0.7x0.7 smd paste+0 mask+0: 1(-0.7,0) 2(0.7,0)
  body extent -1.15,-0.6 1.15,0.6, height 0.25
FP-742792641-MFG [mm]
  rect 0.95x0.7 smd paste+0 mask+0: 1(-0.825,0) 2(0.825,0)
  body extent -0.8,-0.4 0.8,0.4, height 1
FP-ABM8G-MFG [mm]
  rect 1.4x1.2 smd paste+0 mask+0: 1(-1.1,-0.85) 2(1.1,-0.85) 3(1.1,0.85) 4(-1.1,0.85)
  silkscreen extent -2.47,-1.83 1.6,1.83, body extent -1.9,-1.55 1.9,1.55, height 0.25
FP-B3U-1000P-MFG [mm]
  rect 0.8x1.7 smd paste+0 mask+0: 1(-1.7,0) 2(1.7,0)
  silkscreen extent -1.6,-1.35 1.6,1.35, body extent -2,-1.26 2,1.24, height 1.6
FP-C0402-BB-MFG [mm]
  rect 0.52x0.52 smd paste+0 mask+0: 1(-0.4,0) 2(0.4,0)
  silkscreen extent -0.5,-0.64 0.5,0.64, body extent -0.5,-0.25 0.5,0.25, height 0.55
FP-C1005-050-0_05-IPC_C [mil]
  rect 21.23x18.6 smd paste+0 mask+0: 1(-14.43,0) 2(14.43,0)
  body extent -20,-10 20,10, height 22
FP-C1005-050-0_15-MFG [mm]
  rect 0.4x0.5 smd paste+0 mask+0: 1(-0.4,0) 2(0.4,0)
  silkscreen extent -0.5,-0.72 0.5,0.72, body extent -0.5,-0.25 0.5,0.25, height 0.55
FP-CL05A106MP5NUNC-MFG [mm]
  rect 0.45x0.675 smd paste+0 mask+0: 1(-0.463,0) 2(0.463,0)
  body extent -0.5,-0.25 0.5,0.25, height 0.7
FP-CL10-IPC_C [mil]
  rect 29.85x31.97 smd paste+0 mask+0: 1(-24.68,0) 2(24.69,0)
  body extent -31,-16 31,16, height 36
FP-CL165-IPC_C [mil]
  rect 20.29x18.6 smd paste+0 mask+0: 1(-14.9,0) 2(14.9,0)
  silkscreen extent -25,-27 25,27, body extent -29,-15 29,15, height 10
FP-DFE252012C-IPC_A [mil]
  rect 61.22x90.8 smd paste+0 mask+0: 1(-44.32,0) 2(44.32,0)
  silkscreen extent -75,-61 75,61, body extent -95,-65 95,65, height 10
FP-LQG15HH_02-IPC_C [mil]
  rect 20.29x18.6 smd paste+0 mask+0: 1(-14.9,0) 2(14.9,0)
  silkscreen extent -54,-27 25,27, body extent -29,-15 29,15, height 10
FP-LTST-C190GKT-MFG [mm]
  rect 0.8x0.8 smd paste+0 mask+0: 1(-0.75,0) 2(0.75,0)
  silkscreen extent -1.92,-0.85 0.85,0.85, body extent -1.25,-0.55 1.25,0.55, height 0.25
FP-PESD0402-MFG [mm]
  rect 0.85x0.65 smd paste+0 mask+0: 1(-0.625,0) 2(0.625,0)
  body extent -1.15,-0.43 1.15,0.43, height 0.25
FP-RQR0014A-MFG [mm]
  rrect40% 0.625x0.25 smd paste+0 mask+0: 1(-1.038,0.5) 2(-1.038,0) 3(-1.038,-0.5) 8(1.038,-0.5) 10(1.038,0.5)
  rrect40% 0.25x0.675 smd paste+0 mask+0: 4(-0.75,-1.212) 5(-0.25,-1.212) 7(0.75,-1.212) 11(0.75,1.212) 13(-0.25,1.212) 14(-0.75,1.212)
  rrect40% 0.25x0.975 smd paste+0 mask+0: 6(0.25,-1.062) 12(0.25,1.062)
  rrect40% 1.225x0.25 smd paste+0 mask+0: 9(0.737,0)
  silkscreen extent -2.2,-1.55 1.35,2.39, body extent -1.45,-1.65 1.45,1.65, height 0.25
FP-RT9080-33GJ5-IPC_C [mil]
  rect 48.02x23.17 smd paste+0 mask+0: 1(-41.07,36.99)
  rrect100% 48.02x23.17 smd paste+0 mask+0: 2(-41.07,0) 3(-41.07,-36.99) 4(41.07,-36.99) 5(41.07,36.99)
  silkscreen extent -90,-57 3,57, body extent -69,-61 69,61, height 10
FP-SiT5001-3-MFG [mm]
  rect 1.5x1.6 smd paste+0 mask+0: 1(-1.27,-1.1) 2(1.27,-1.1) 3(1.27,1.1) 4(-1.27,1.1)
  silkscreen extent -2.52,-2.58 2.52,1.63, body extent -2.63,-2 2.63,2, height 0.25
FP-SKY13585-679LF-MFG [mm]
  rect 0.33x0.15 smd paste+0 mask+0: 1(-0.485,0.35) 3(-0.485,-0.35) 4(0.485,-0.35) 5(0.485,0) 6(0.485,0.35)
  round 0.27 smd paste+0 mask+0: 2(-0.097,0)
  L01-TOP region: -0.285,-0.075 -0.65,-0.075 -0.65,0.075 -0.285,0.075 -0.257,0.074 -0.231,0.082 -0.21,0.1 -0.21,0.1 -0.1,0.2 -0.083,0.223 -0.075,0.25 -0.075,0.25 -0.075,0.65 0.075,0.65 0.075,0.275 0.083,0.245 0.102,0.22 0.102,0.22 0.122,0.195 0.13,0.165 0.13,0.165 0.13,-0.165 0.122,-0.195 0.102,-0.22 0.102,-0.22 0.083,-0.245 0.075,-0.275 0.075,-0.275 0.075,-0.65 -0.075,-0.65 -0.075,-0.25 -0.083,-0.223 -0.1,-0.2 -0.1,-0.2 -0.21,-0.1 -0.231,-0.082 -0.257,-0.074 -0.285,-0.075 -0.285,-0.075
  silkscreen extent -1.23,-1.02 0.53,1.02, body extent -0.75,-0.75 0.75,0.75, height 0.25
FP-SMA-J-P-H-ST-MT1-MFG [mm]
  round 1.73 smd paste+0 mask+0: 1(0,0)
  round 2.3 hole 1.5 paste-2539.97 mask+0: 2(-2.665,2.665) 3(2.665,2.665) 4(-2.665,-2.665) 5(2.665,-2.665)
  silkscreen extent -3.96,-3.24 3.24,3.24, body extent -3.92,-3.92 3.92,3.92, height 0.25
FP-U_FL-R-SMT-1_10-MFG [mm]
  rect 1x1.05 smd paste-1000 mask+0: 1(0,1.525)
  rect 1.05x2.2 smd paste-1000 mask+0: 2(-1.475,0) 3(1.475,0)
  silkscreen extent -0.58,-1.38 0.58,-1.38, body extent -2.1,-1.48 2.1,2.15, height 0.25
IC57_RP2040 [mil]
  rect 32x7 smd paste+0 mask+0: 1(-134,102.36) 2(-134,86.61) 3(-134,70.87) 4(-134,55.12) 5(-134,39.37) 6(-134,23.62) 7(-134,7.87) 8(-134,-7.87) 9(-134,-23.62) 10(-134,-39.37) 11(-134,-55.12) 12(-134,-70.87) 13(-134,-86.61) 14(-134,-102.36) 29(134,-102.36) 30(134,-86.61) 31(134,-70.87) 32(134,-55.12) 33(134,-39.37) 34(134,-23.62) 35(134,-7.87) 36(134,7.87) 37(134,23.62) 38(134,39.37) 39(134,55.12) 40(134,70.87) 41(134,86.61) 42(134,102.36)
  rect 7x32 smd paste+0 mask+0: 15(-102.36,-134) 16(-86.61,-134) 17(-70.87,-134) 18(-55.12,-134) 19(-39.37,-134) 20(-23.62,-134) 21(-7.87,-134) 22(7.87,-134) 23(23.62,-134) 24(39.37,-134) 25(55.12,-134) 26(70.87,-134) 27(86.61,-134) 28(102.36,-134) 43(102.36,134) 44(86.61,134) 45(70.87,134) 46(55.12,134) 47(39.37,134) 48(23.62,134) 49(7.87,134) 50(-7.87,134) 51(-23.62,134) 52(-39.37,134) 53(-55.12,134) 54(-70.87,134) 55(-86.61,134) 56(-102.36,134)
  rect 126x126 smd paste-63 mask+0: 57(0,0)
  silkscreen extent -170,-170 170,170, body extent -138,-138 138,138, height 35
MCHP-SOIC-SN8_N [mm] "SOIC, 8-Leads, Body 4.9x3.9mm, Pitch 1.27mm, IPC Medium Density"
  oval 2.05x0.6 smd: 1(-2.425,1.905) 2(-2.425,0.635) 3(-2.425,-0.635) 4(-2.425,-1.905) 5(2.425,-1.905) 6(2.425,-0.635) 7(2.425,0.635) 8(2.425,1.905)
  silkscreen extent -2.55,-2.45 1,2.88, body extent -1.95,-2.45 1.95,2.45, height 1.75
NBG48P1_REN [mil]
  rect 32x10 smd paste+0 mask+0: 1(-136,108.27) 2(-136,88.58) 3(-136,68.9) 4(-136,49.21) 5(-136,29.53) 6(-136,9.84) 7(-136,-9.84) 8(-136,-29.53) 9(-136,-49.21) 10(-136,-68.9) 11(-136,-88.58) 12(-136,-108.27) 25(136,-108.27) 26(136,-88.58) 27(136,-68.9) 28(136,-49.21) 29(136,-29.53) 30(136,-9.84) 31(136,9.84) 32(136,29.53) 33(136,49.21) 34(136,68.9) 35(136,88.58) 36(136,108.27)
  rect 10x32 smd paste+0 mask+0: 13(-108.27,-136) 14(-88.58,-136) 15(-68.9,-136) 16(-49.21,-136) 17(-29.53,-136) 18(-9.84,-136) 19(9.84,-136) 20(29.53,-136) 21(49.21,-136) 22(68.9,-136) 23(88.58,-136) 24(108.27,-136) 37(108.27,136) 38(88.58,136) 39(68.9,136) 40(49.21,136) 41(29.53,136) 42(9.84,136) 43(-9.84,136) 44(-29.53,136) 45(-49.21,136) 46(-68.9,136) 47(-88.58,136) 48(-108.27,136)
  rect 226x226 smd paste-113 mask+0: 49(0,0)
  silkscreen extent -172,-172 172,172, body extent -140,-140 140,140, height 32
ONSC-SOD-923-2-514AB-01_B_V [mm] "SOD, 2-Leads, Body 0.8x0.6mm"
  rect 0.3x0.4 smd: 1(-0.45,0) 2(0.45,0)
  silkscreen extent -0.5,0.55 -0.4,0.65, body extent -0.4,-0.3 0.4,0.3, height 0.4
RESC0402(1005)_L [mm] "Chip Resistor, Body 1.0x0.5mm, IPC High Density"
  rect 0.45x0.55 smd: 1(-0.45,0) 2(0.45,0)
  body extent -0.52,-0.27 0.53,0.28, height 0.4
RESC1005X40X25LL05T10 [mm] "Chip Resistor, 2-Leads, Body 1.00x0.50mm, IPC High Density"
  rect 0.5x0.45 smd: 1(-0.375,0) 2(0.375,0)
  body extent -0.53,-0.27 0.53,0.28, height 0.4
RESC1005X40X25LL10T10 [mm] "Chip Resistor, 2-Leads, Body 1.00x0.50mm, IPC High Density"
  rect 0.55x0.5 smd: 1(-0.375,0) 2(0.375,0)
  body extent -0.55,-0.3 0.55,0.3, height 0.4
RESC1005X40X25ML05T05 [mm] "Chip Resistor, 2-Leads, Body 1.05x0.55mm, IPC Low Density"
  rect 0.65x0.65 smd: 1(-0.5,0) 2(0.5,0)
  body extent -0.53,-0.28 0.53,0.28, height 0.4
RESC1005X40X25ML05T10 [mm] "Chip Resistor, 2-Leads, Body 1.00x0.50mm, IPC Low Density"
  rect 0.7x0.65 smd: 1(-0.475,0) 2(0.475,0)
  body extent -0.53,-0.27 0.53,0.28, height 0.4
RESC1005X40X25ML10T10 [mm] "Chip Resistor, 2-Leads, Body 1.00x0.50mm, IPC Low Density"
  rect 0.75x0.7 smd: 1(-0.475,0) 2(0.475,0)
  body extent -0.55,-0.3 0.55,0.3, height 0.4
RESC1005X40X25NL05T05 [mm] "Chip Resistor, 2-Leads, Body 1.00x0.50mm, IPC Medium Density"
  rect 0.55x0.55 smd: 1(-0.45,0) 2(0.45,0)
  body extent -0.53,-0.27 0.53,0.28, height 0.4
RESC1005X40X25NL05T10 [mm] "Chip Resistor, 2-Leads, Body 1.00x0.50mm, IPC Medium Density"
  rect 0.6x0.55 smd: 1(-0.425,0) 2(0.425,0)
  body extent -0.53,-0.27 0.53,0.28, height 0.4
RESC1005X40X25NL10T10 [mm] "Chip Resistor, 2-Leads, Body 1.00x0.50mm, IPC Medium Density"
  rect 0.65x0.6 smd: 1(-0.425,0) 2(0.425,0)
  body extent -0.55,-0.3 0.55,0.3, height 0.4
RUG8_TEX [mm]
  rect 0.58x0.3 smd paste-0.15 mask-0.292: 1(-0.635,0.5) 3(-0.635,-0.5) 5(0.635,-0.5) 7(0.635,0.5)
  rect 0.58x0.25 smd paste-2539.97 mask+0: 2(-0.635,0) 6(0.635,0)
  rect 0.35x0.63 smd paste-2539.97 mask+0: 4(0,-0.435) 8(0,0.435)
  silkscreen extent -1.03,-1.03 1.03,1.03
SITIME_SPL-086-CQFN-010-C07050_REV_DRAFT [mm] "Package information (Page 9): https://www.sitime.com/support/resource-library/datasheets/sit5501-datasheet"
  rect 0.85x1.25 smd paste+0 mask+0.05: 1(-1.27,2.875) 5(-1.27,-2.875) 6(1.27,-2.875) 10(1.27,2.875)
  rect 1.25x0.65 smd paste+0 mask+0.05: 2(-1.875,1.27) 3(-1.875,0) 4(-1.875,-1.27) 7(1.875,-1.27) 8(1.875,0) 9(1.875,1.27)
  silkscreen extent -2.6,-3.5 2.6,3.5, body extent -2.5,-3.5 2.5,3.5, height 2.3
SMD-0402 [mm] "Chip Inductor, 2-Leads, Body 1.0x0.5mm"
  rect 0.675x0.6 smd: 1(-0.6,0) 2(0.6,0)
  body extent -0.5,-0.25 0.5,0.25, height 0.49
USB-MICRO-B_V [mm] "USB, MICRO B, Body 7.491x4.695 mm, Pitch 0.65 mm"
  rect 0.4x1.35 smd: 1(-1.3,1.35) 2(-0.65,1.35) 3(0,1.35) 4(0.65,1.35) 5(1.3,1.35)
  round 1.45 hole 0.85: 6(-2.5,1.35) 7(2.5,1.35)
  rrect50% 0x0 hole 0.6 slot 1.3 at 90 deg: 8(-3.5,-1.35) 11(3.5,-1.35)
  rect 1.5x1.9 smd: 9(-1,-1.35) 10(1,-1.35)
  L01-TOP circle w0.5: c3.6,-0.9 r0.25
  L01-TOP circle w0.5: c3.6,-1.8 r0.25
  L01-TOP circle w0.5: c-3.6,-0.9 r0.25
  L01-TOP circle w0.5: c-3.6,-1.8 r0.25
  L01-TOP region: -2.3,-2.3 -2.3,-0.4 -3.6,-0.4 -3.6,-2.3
  L01-TOP region: 2.3,-0.4 2.3,-2.3 3.6,-2.3 3.6,-0.4
  L01-TOP region: 3.6,-0.9 3.6,-1.8 4.1,-1.8 4.1,-0.9
  L01-TOP region: -3.6,-1.8 -3.6,-0.9 -4.1,-0.9 -4.1,-1.8
  silkscreen extent -3.75,-3.5 3.75,2.23, body extent -4.1,-3.9 4.1,1.5, height 2.67
WINB-SOIC-8_M [mm] "SOIC, 8-Leads, Body 5.4x5.4mm, Pitch 1.27mm, IPC Low Density"
  oval 1.9x0.65 smd: 1(-3.65,1.905) 2(-3.65,0.635) 3(-3.65,-0.635) 4(-3.65,-1.905) 5(3.65,-1.905) 6(3.65,-0.635) 7(3.65,0.635) 8(3.65,1.905)
  silkscreen extent -3.77,-2.7 2.3,2.9, body extent -2.7,-2.7 2.7,2.7, height 2.16

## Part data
C1 C9 C13 C19 C22 C24 C40 C41 C42 C44 C58 C62 C64 C68 C71 C73 C77 C80 C84 C87 C90 C92 C94 C97 C100 C102 C104 C107 C109 C112 C114: library part CMP-13271-000002-1, "CAP CER 10UF 10V X5R 0402", Capacitance=10uF, Manufacturer=Samsung, Manufacturer Part Number=CL05A106MP5NUNC, Temperature="-55°C to +85°C", Temperature Characteristic=X5R, Temperature Coefficient=15%, Temperature Range High=+85°C, Temperature Range Low=-55°C, Tolerance=20%, Voltage Rating=10V
C2: library part CMP-2010-01745-1, Manufacturer=Multicomp, Part Number=MC000322
C3 C6 C7 C12 C16 C17 C20 C29 C30 C32 C33 C34 C35 C39 C43 C46 C47 C50 C51: library part CMP-1034-02068-3, "CAP CER 0.1UF 16V 5% X7R 0402", Capacitance="0.10 μF", Manufacturer=Kemet, Manufacturer Part Number=C0402C104J4RACTU, Package=C0402-BB, Temperature="-55°C to +125°C", Temperature Characteristic=X7R, Temperature Coefficient=15%, Temperature Range High=+125°C, Temperature Range Low=-55°C, Tolerance=0.05, Voltage Rating="16 V"
C4: library part CMP-2010-00182-2, "General Purpose Ceramic Capacitor, 0201, 1nF, 10%, X7R, 15%, 16V", Capacitance=1nF, Case Code (Imperial)=0201, Case Code (Metric)=0603, Dielectric=X7R, Dielectric Material=Ceramic, Insulation Resistance=100GR, Max Operating Temperature=125°C, Min Operating Temperature=-55°C, Package Quantity=1, Tolerance=10%, Voltage=16V
C5: library part CMP-13271-000387-1, "Cap Ceramic 10nF 50V X7R ±10% SMD 0402 +125°C Paper T/R", Capacitance=10nF, Case Code (Imperial)=0402, Case Code (Metric)=1005, Dielectric=X7R, Max Operating Temperature=125°C, Min Operating Temperature=-55°C, Package Quantity=1, Tolerance=10%, Voltage=50V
